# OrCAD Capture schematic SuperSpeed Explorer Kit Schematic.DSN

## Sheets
1 PAGE04: FX3 POWER: size A; title: FX3 DVK; rev: 2.0
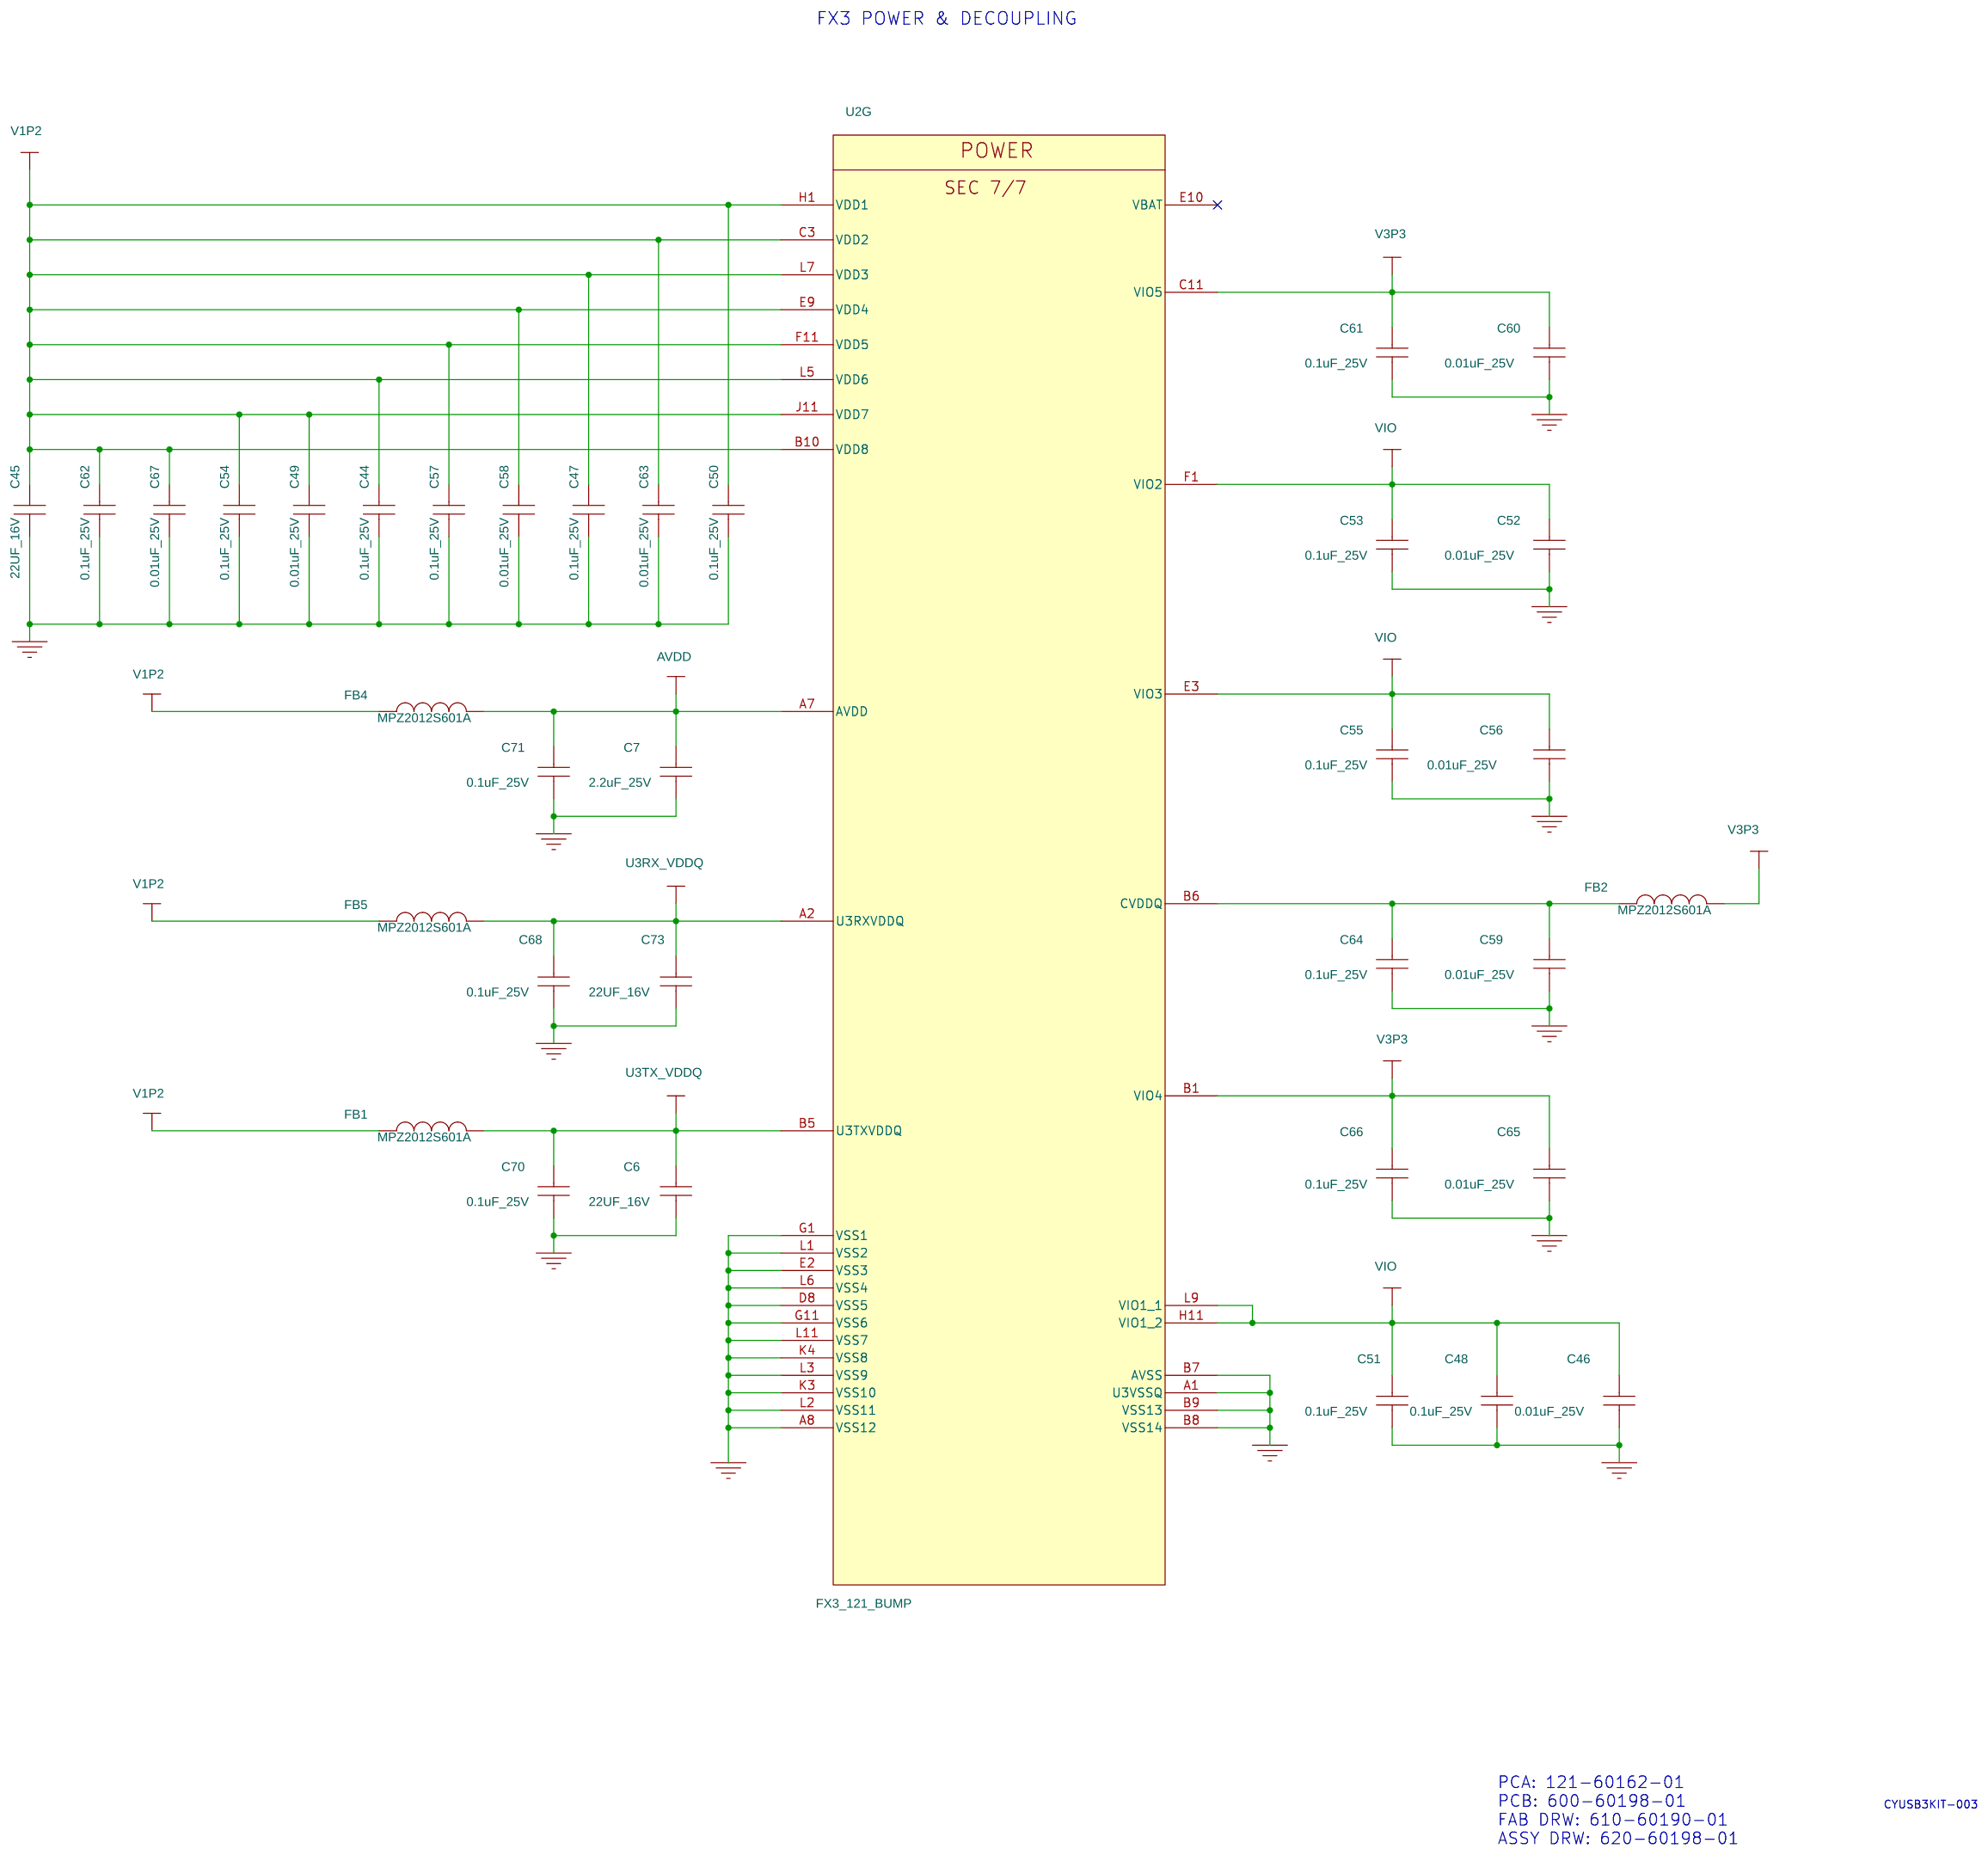
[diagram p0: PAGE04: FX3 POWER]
2 PAGE05: IO PORT1: size A
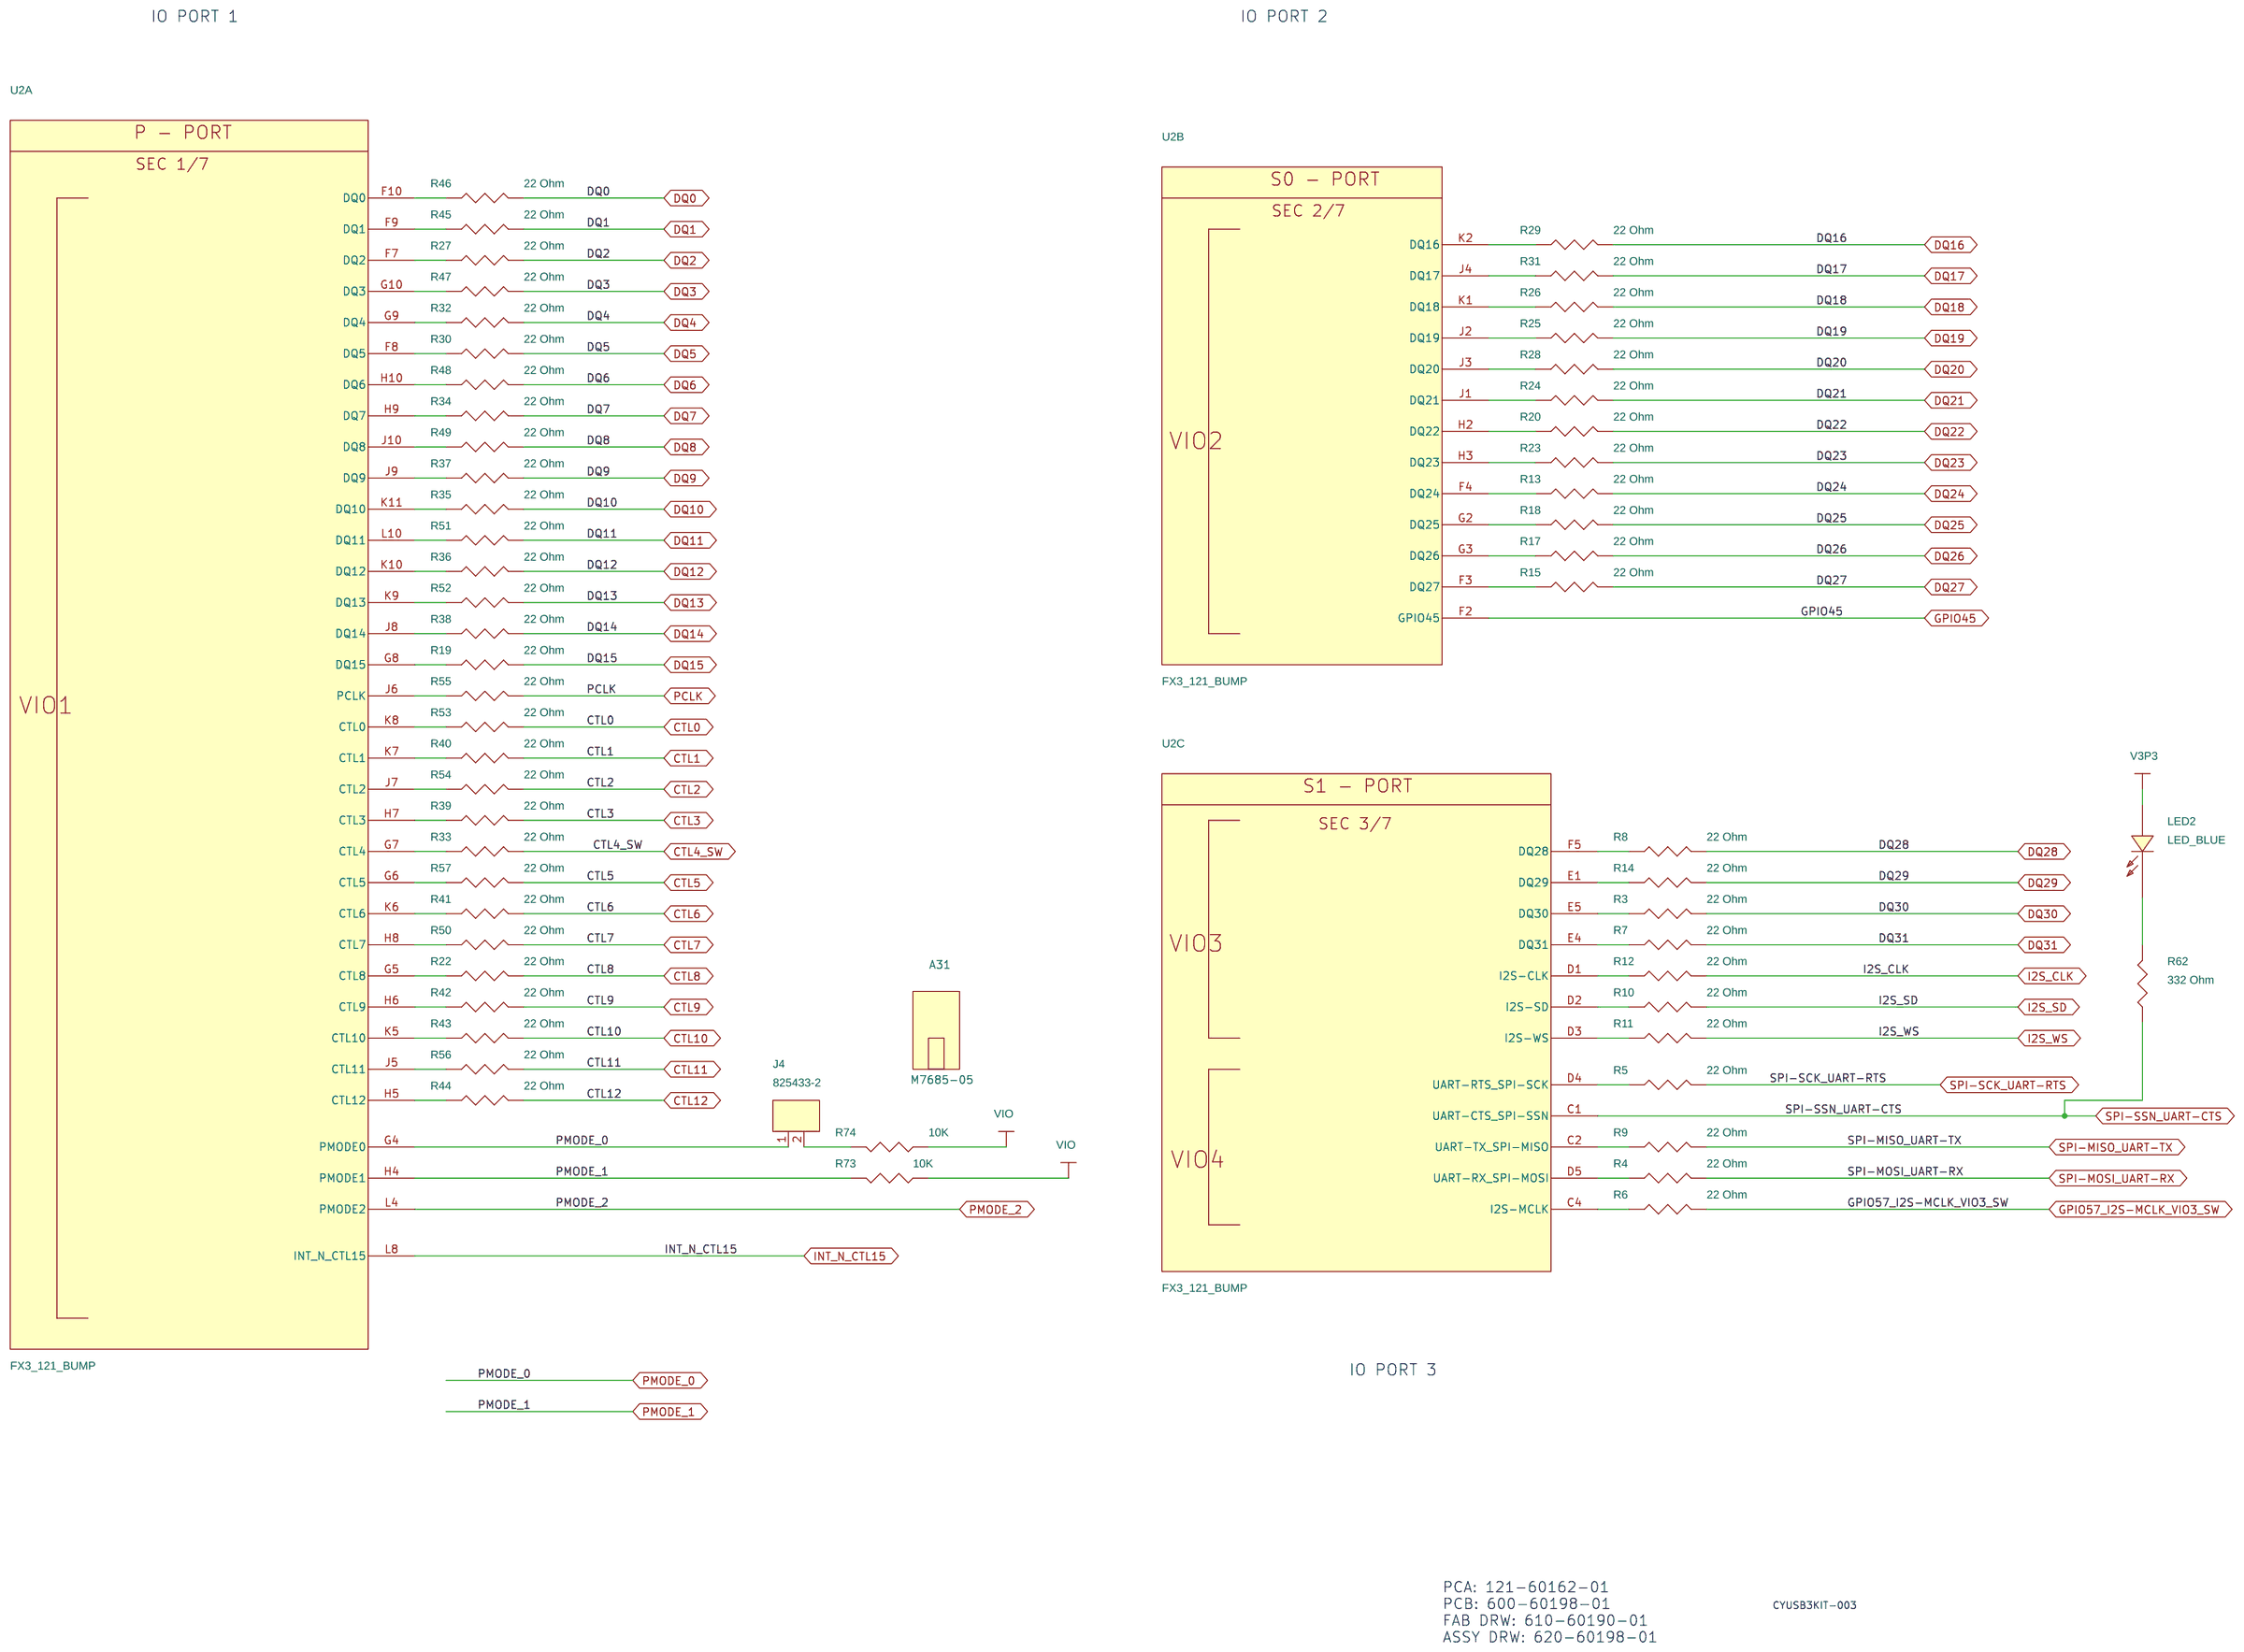
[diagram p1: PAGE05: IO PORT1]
3 PAGE07: SRAM: size A
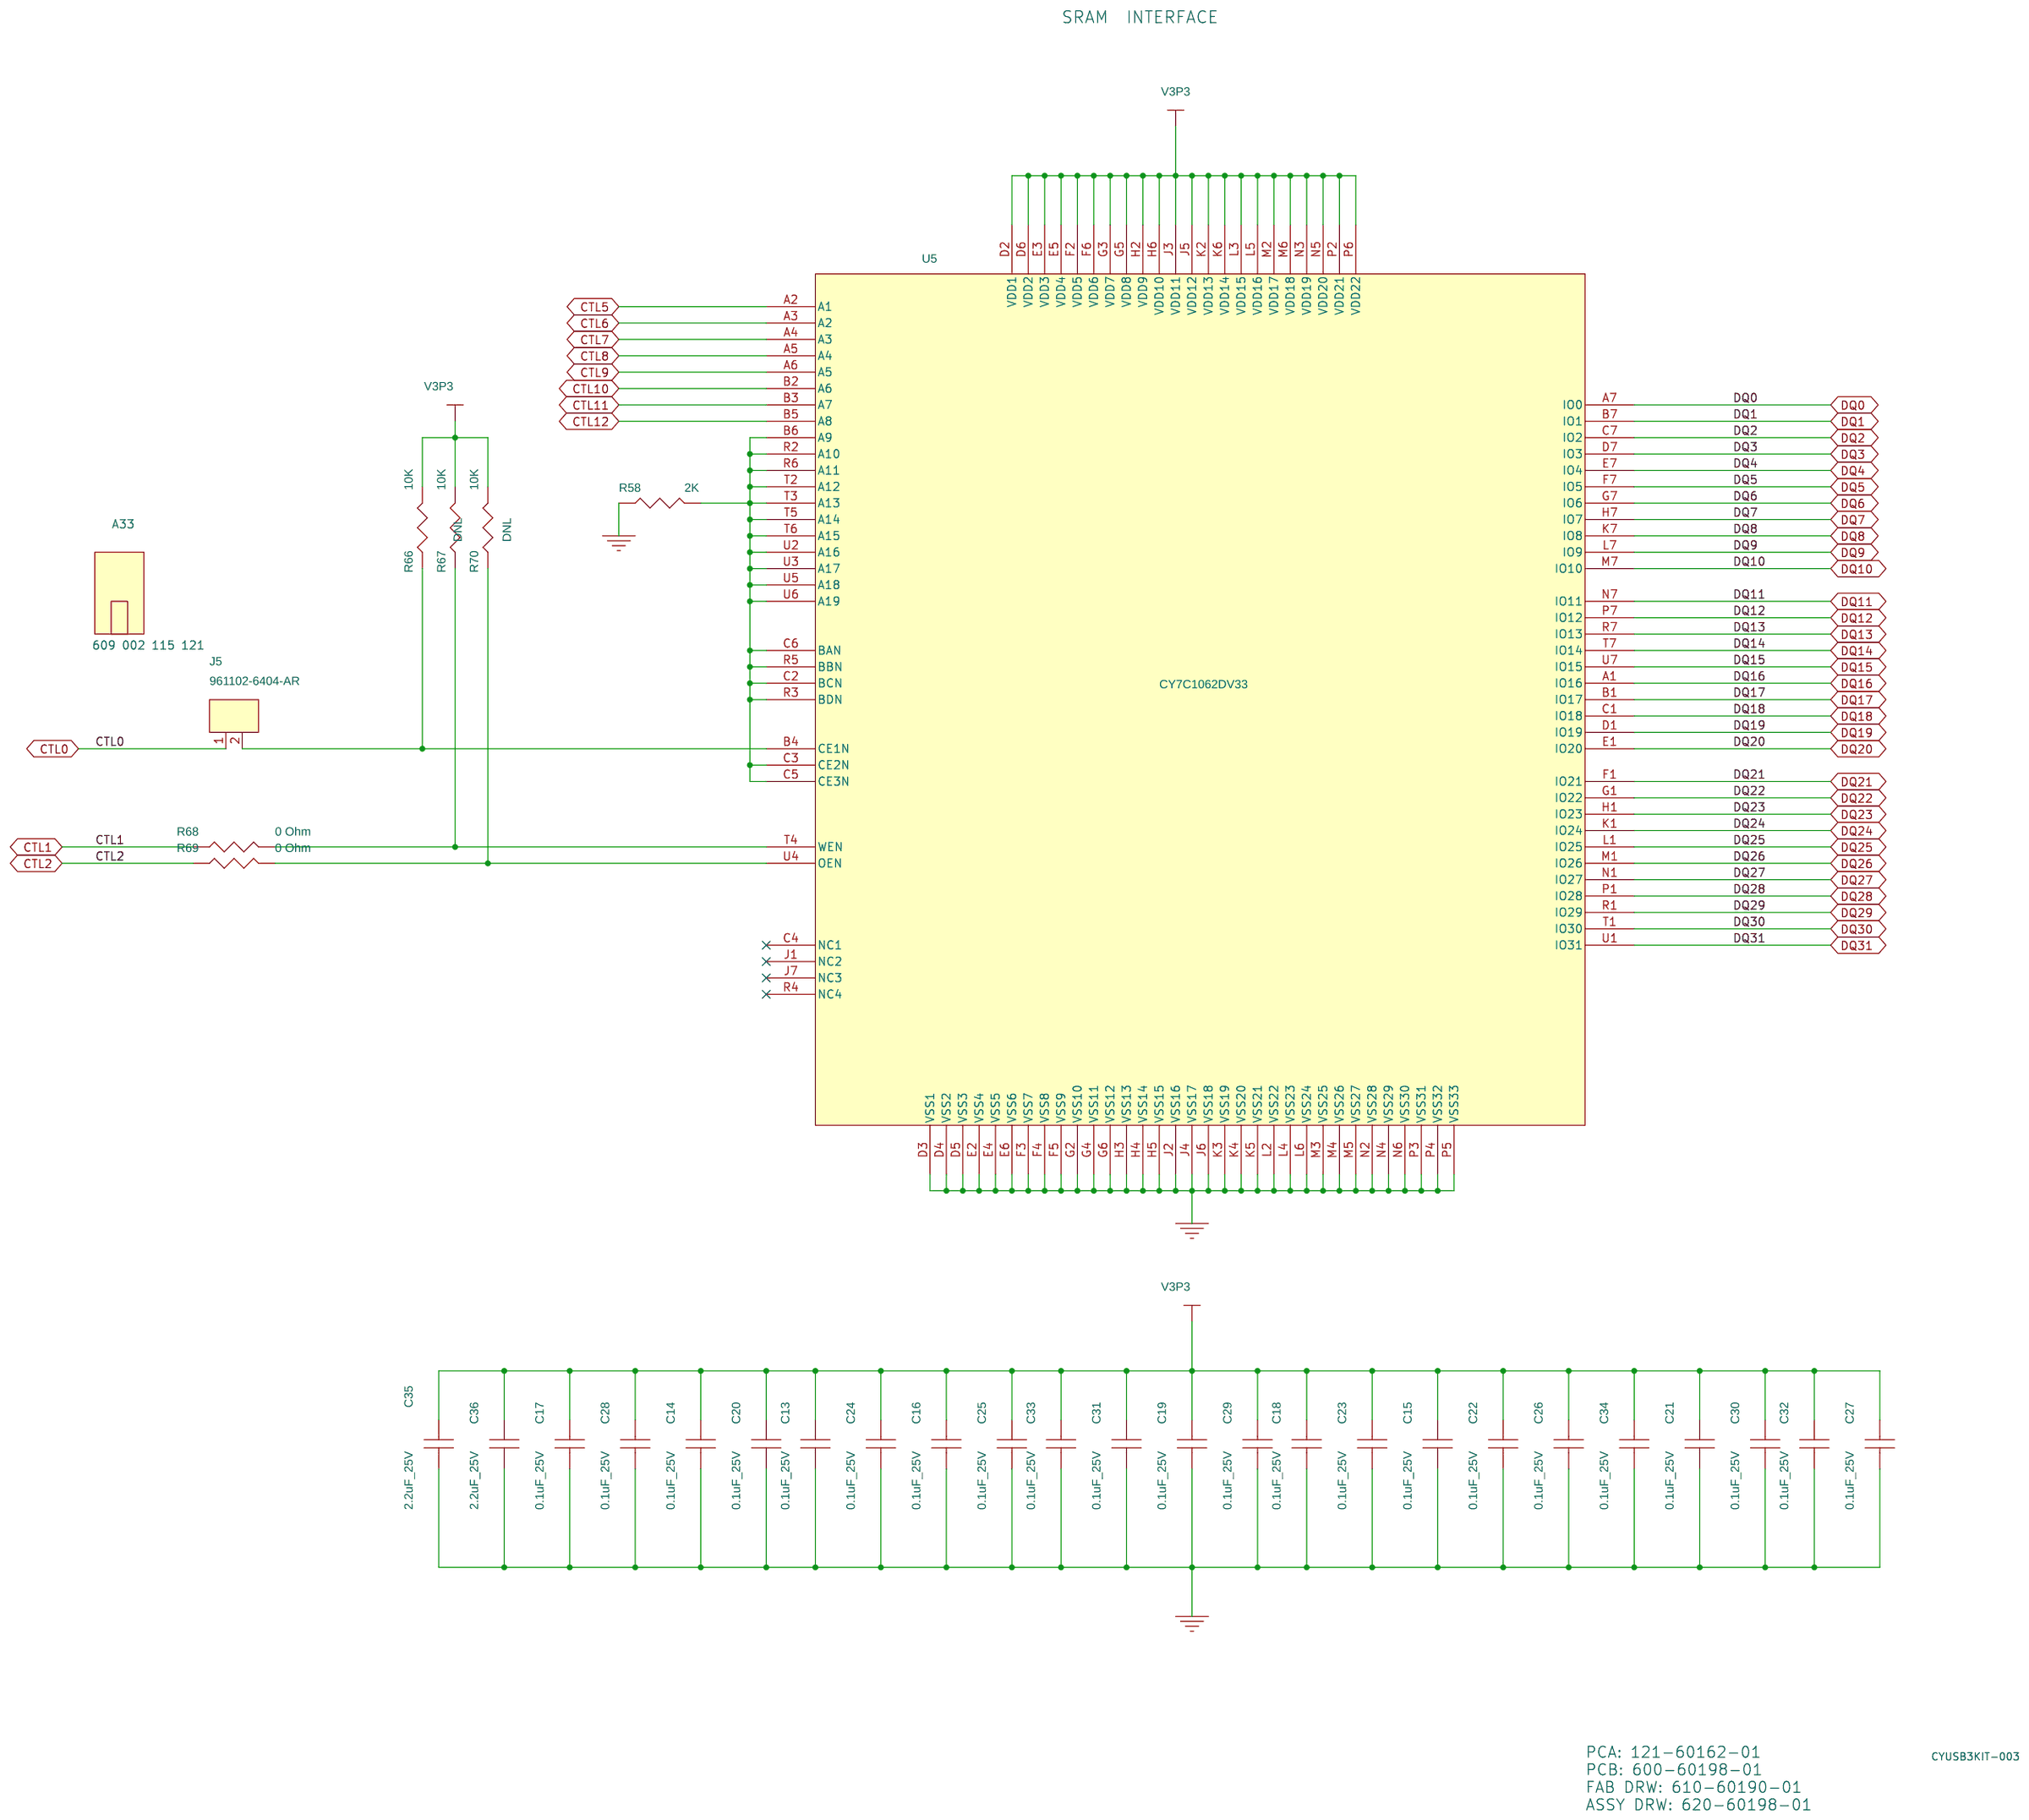
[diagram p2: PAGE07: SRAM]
4 PAGE03: FX3 CLOCK: size A
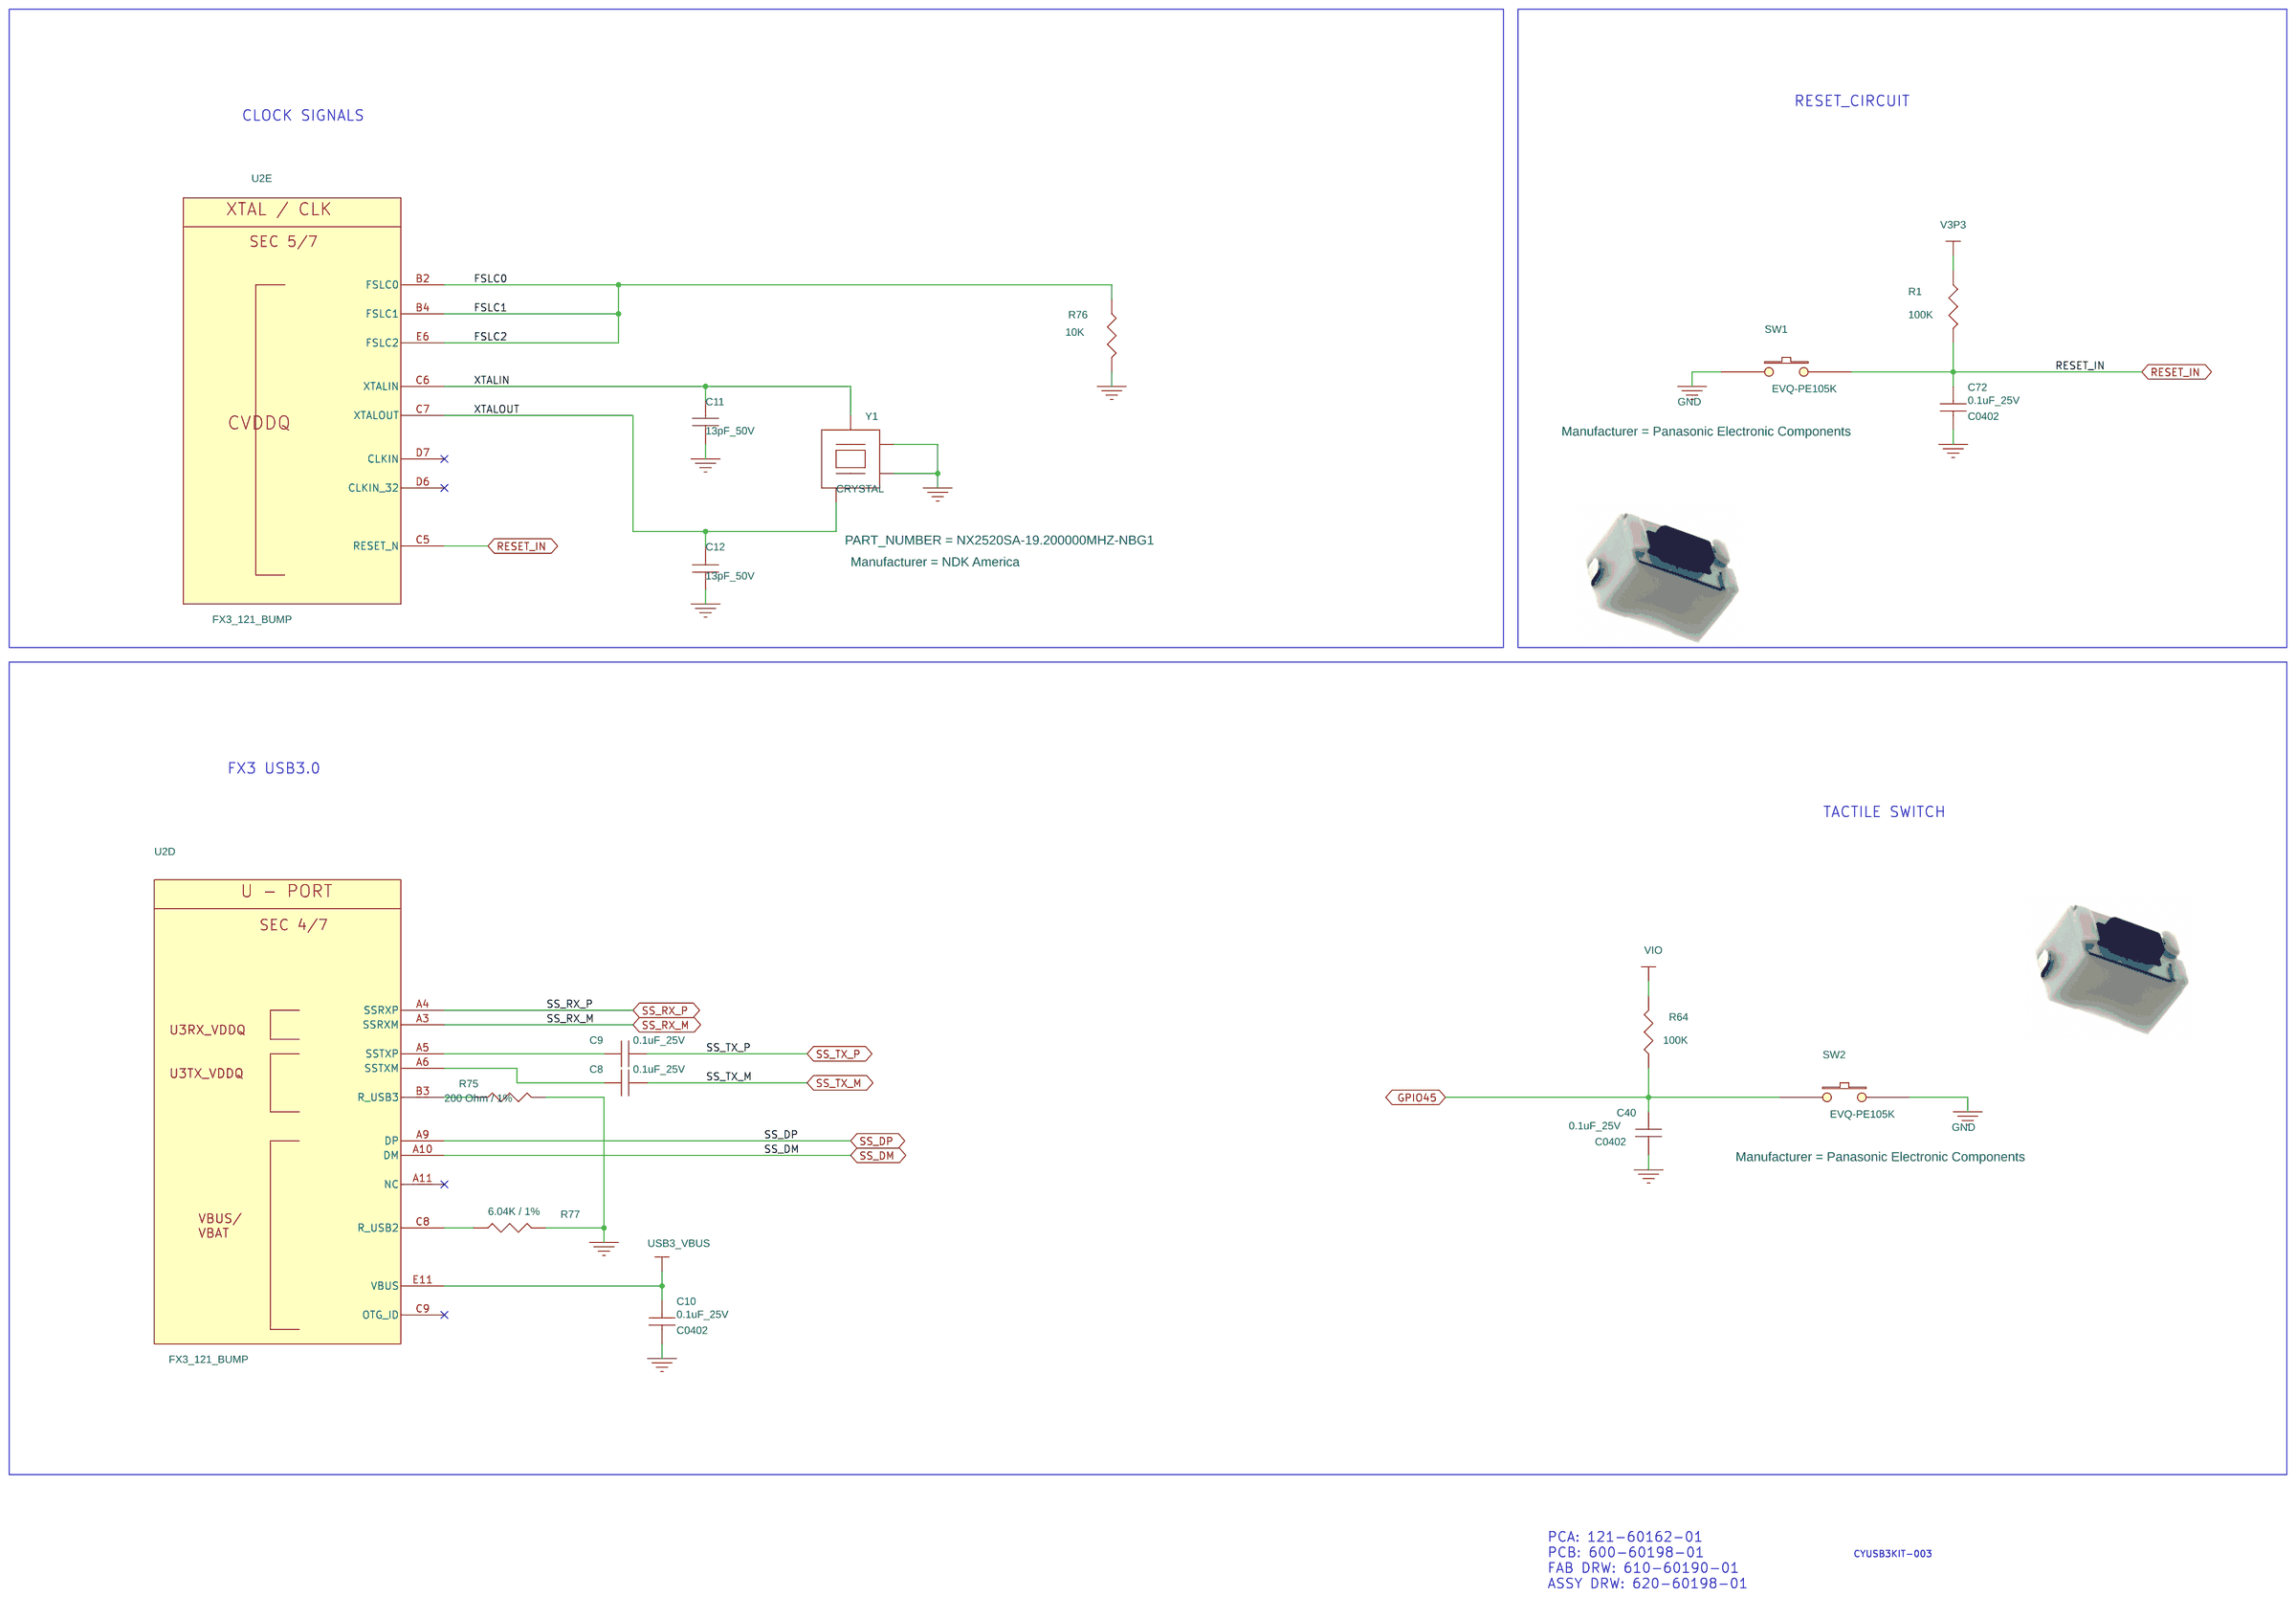
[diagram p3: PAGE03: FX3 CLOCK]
5 PAGE08:UART & JTAG: size A
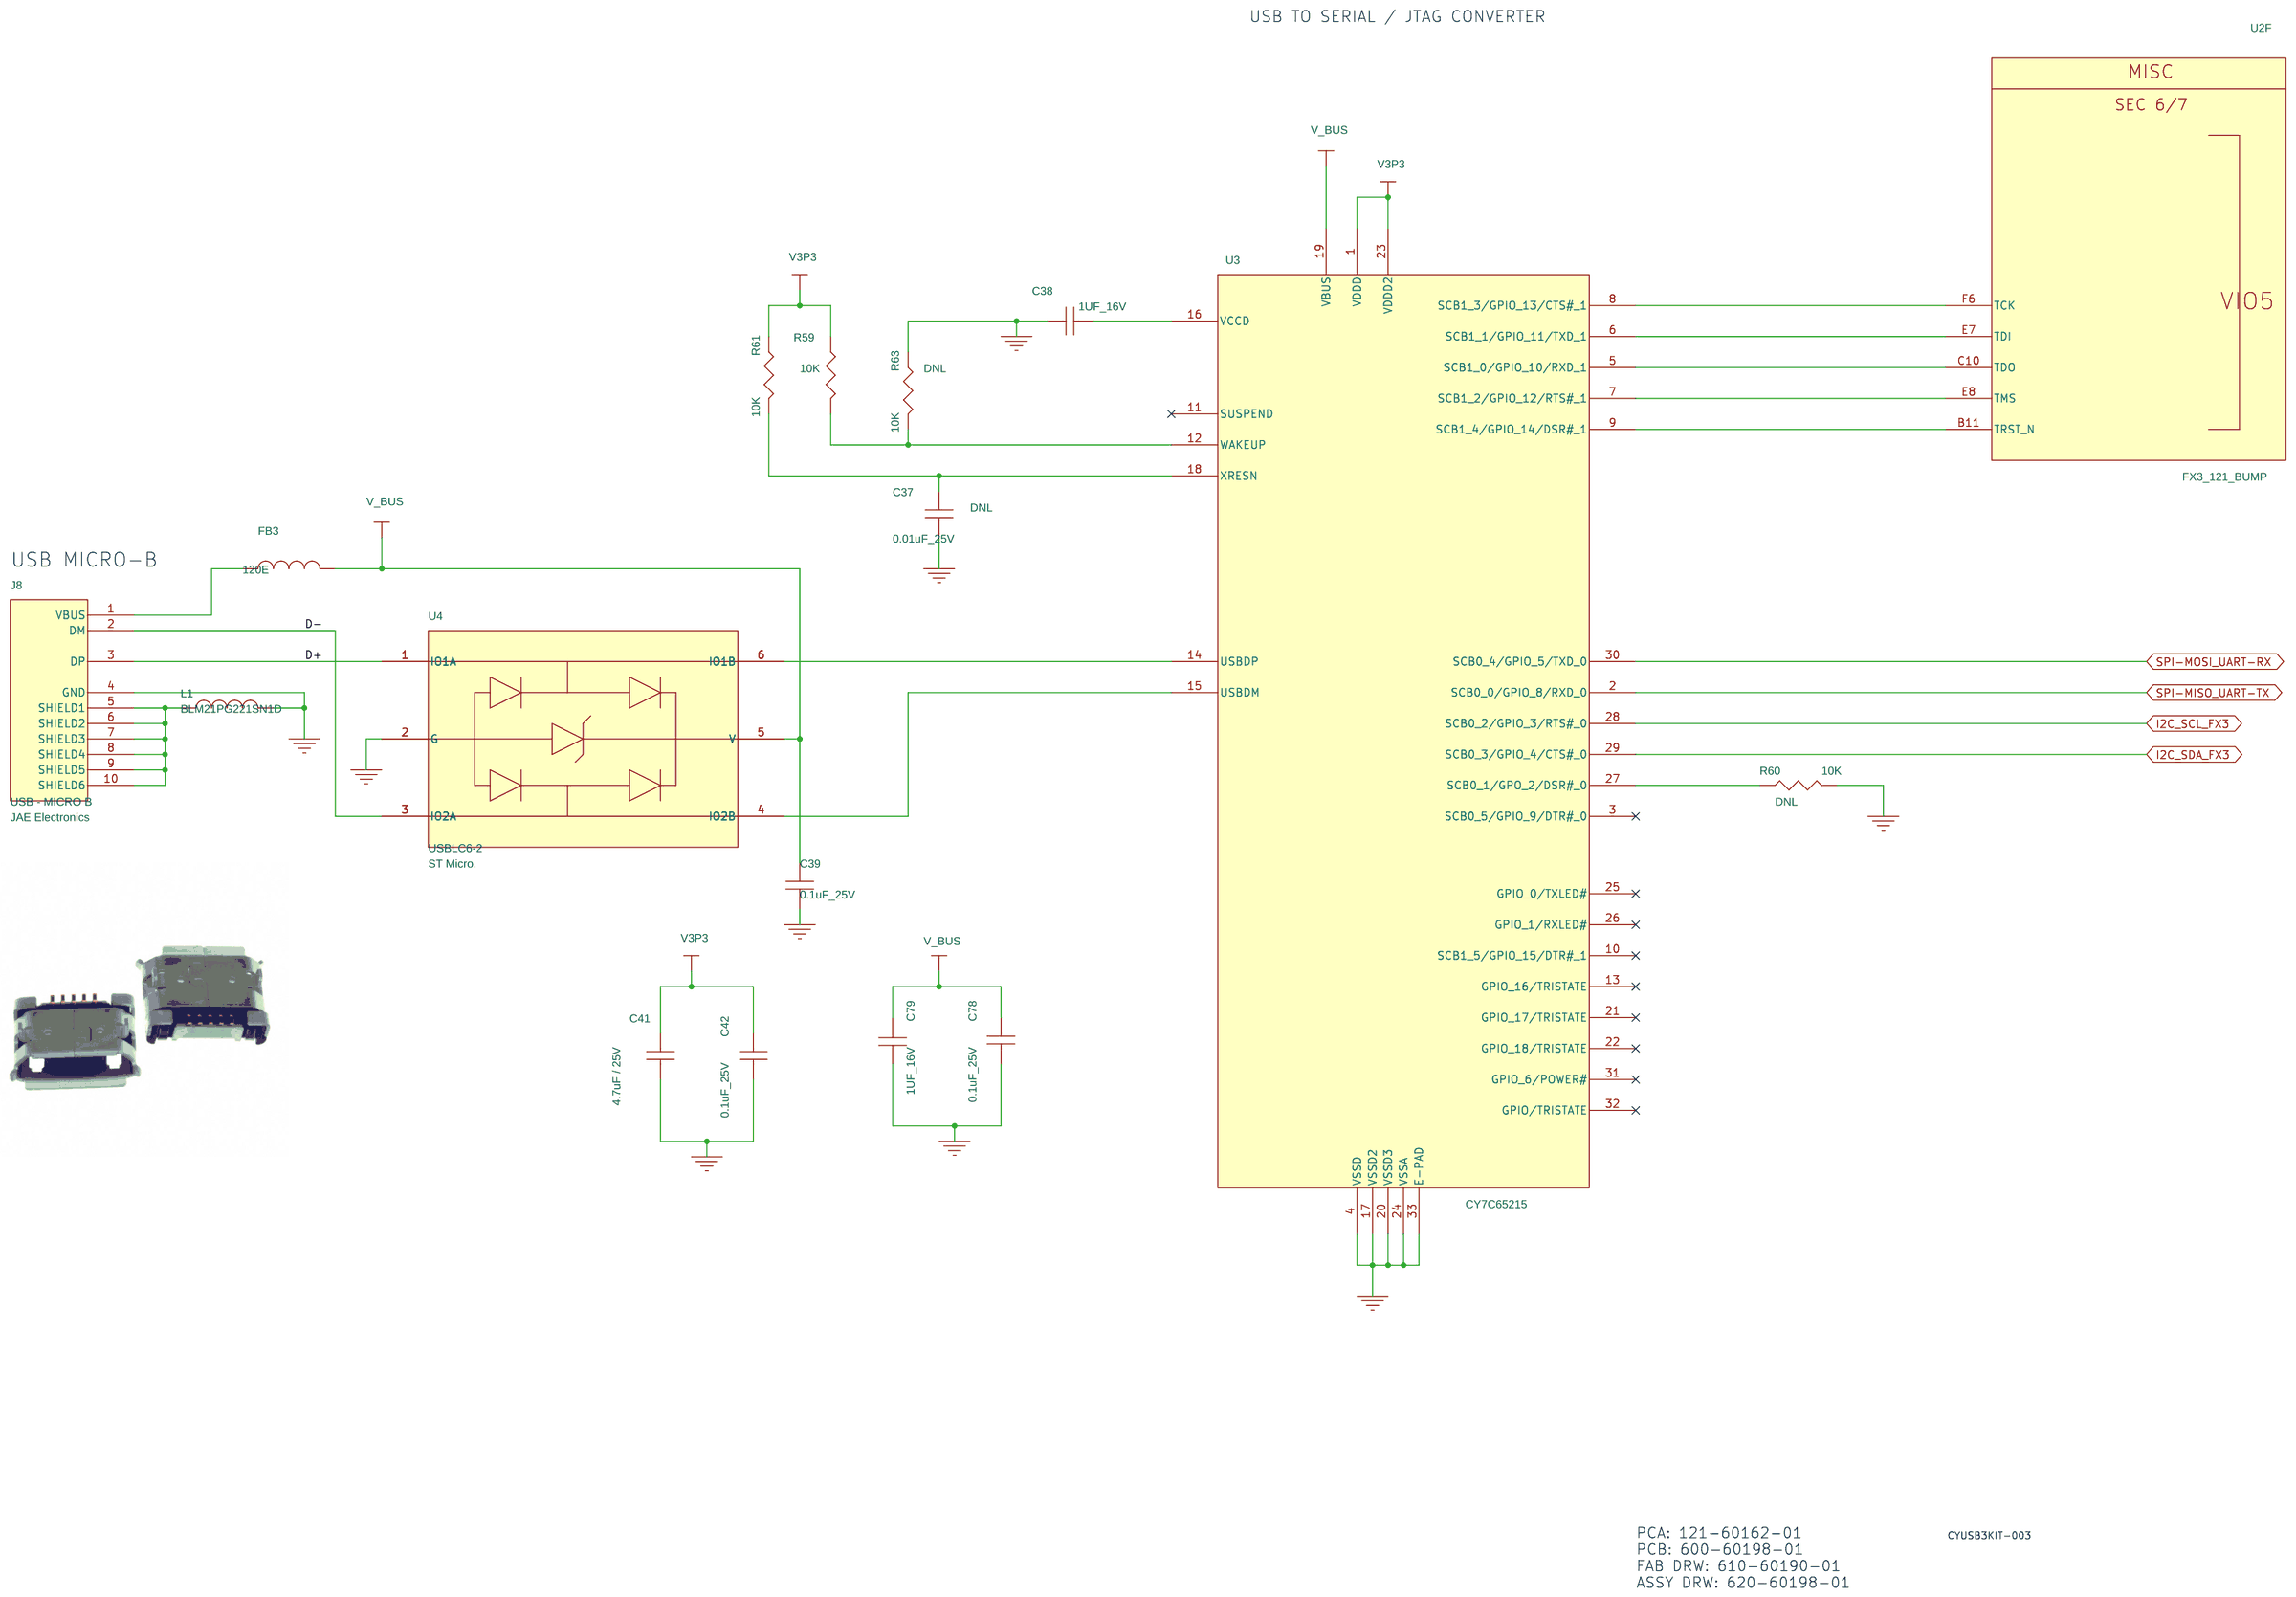
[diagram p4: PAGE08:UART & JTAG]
6 PAGE01: INDEX PAGE
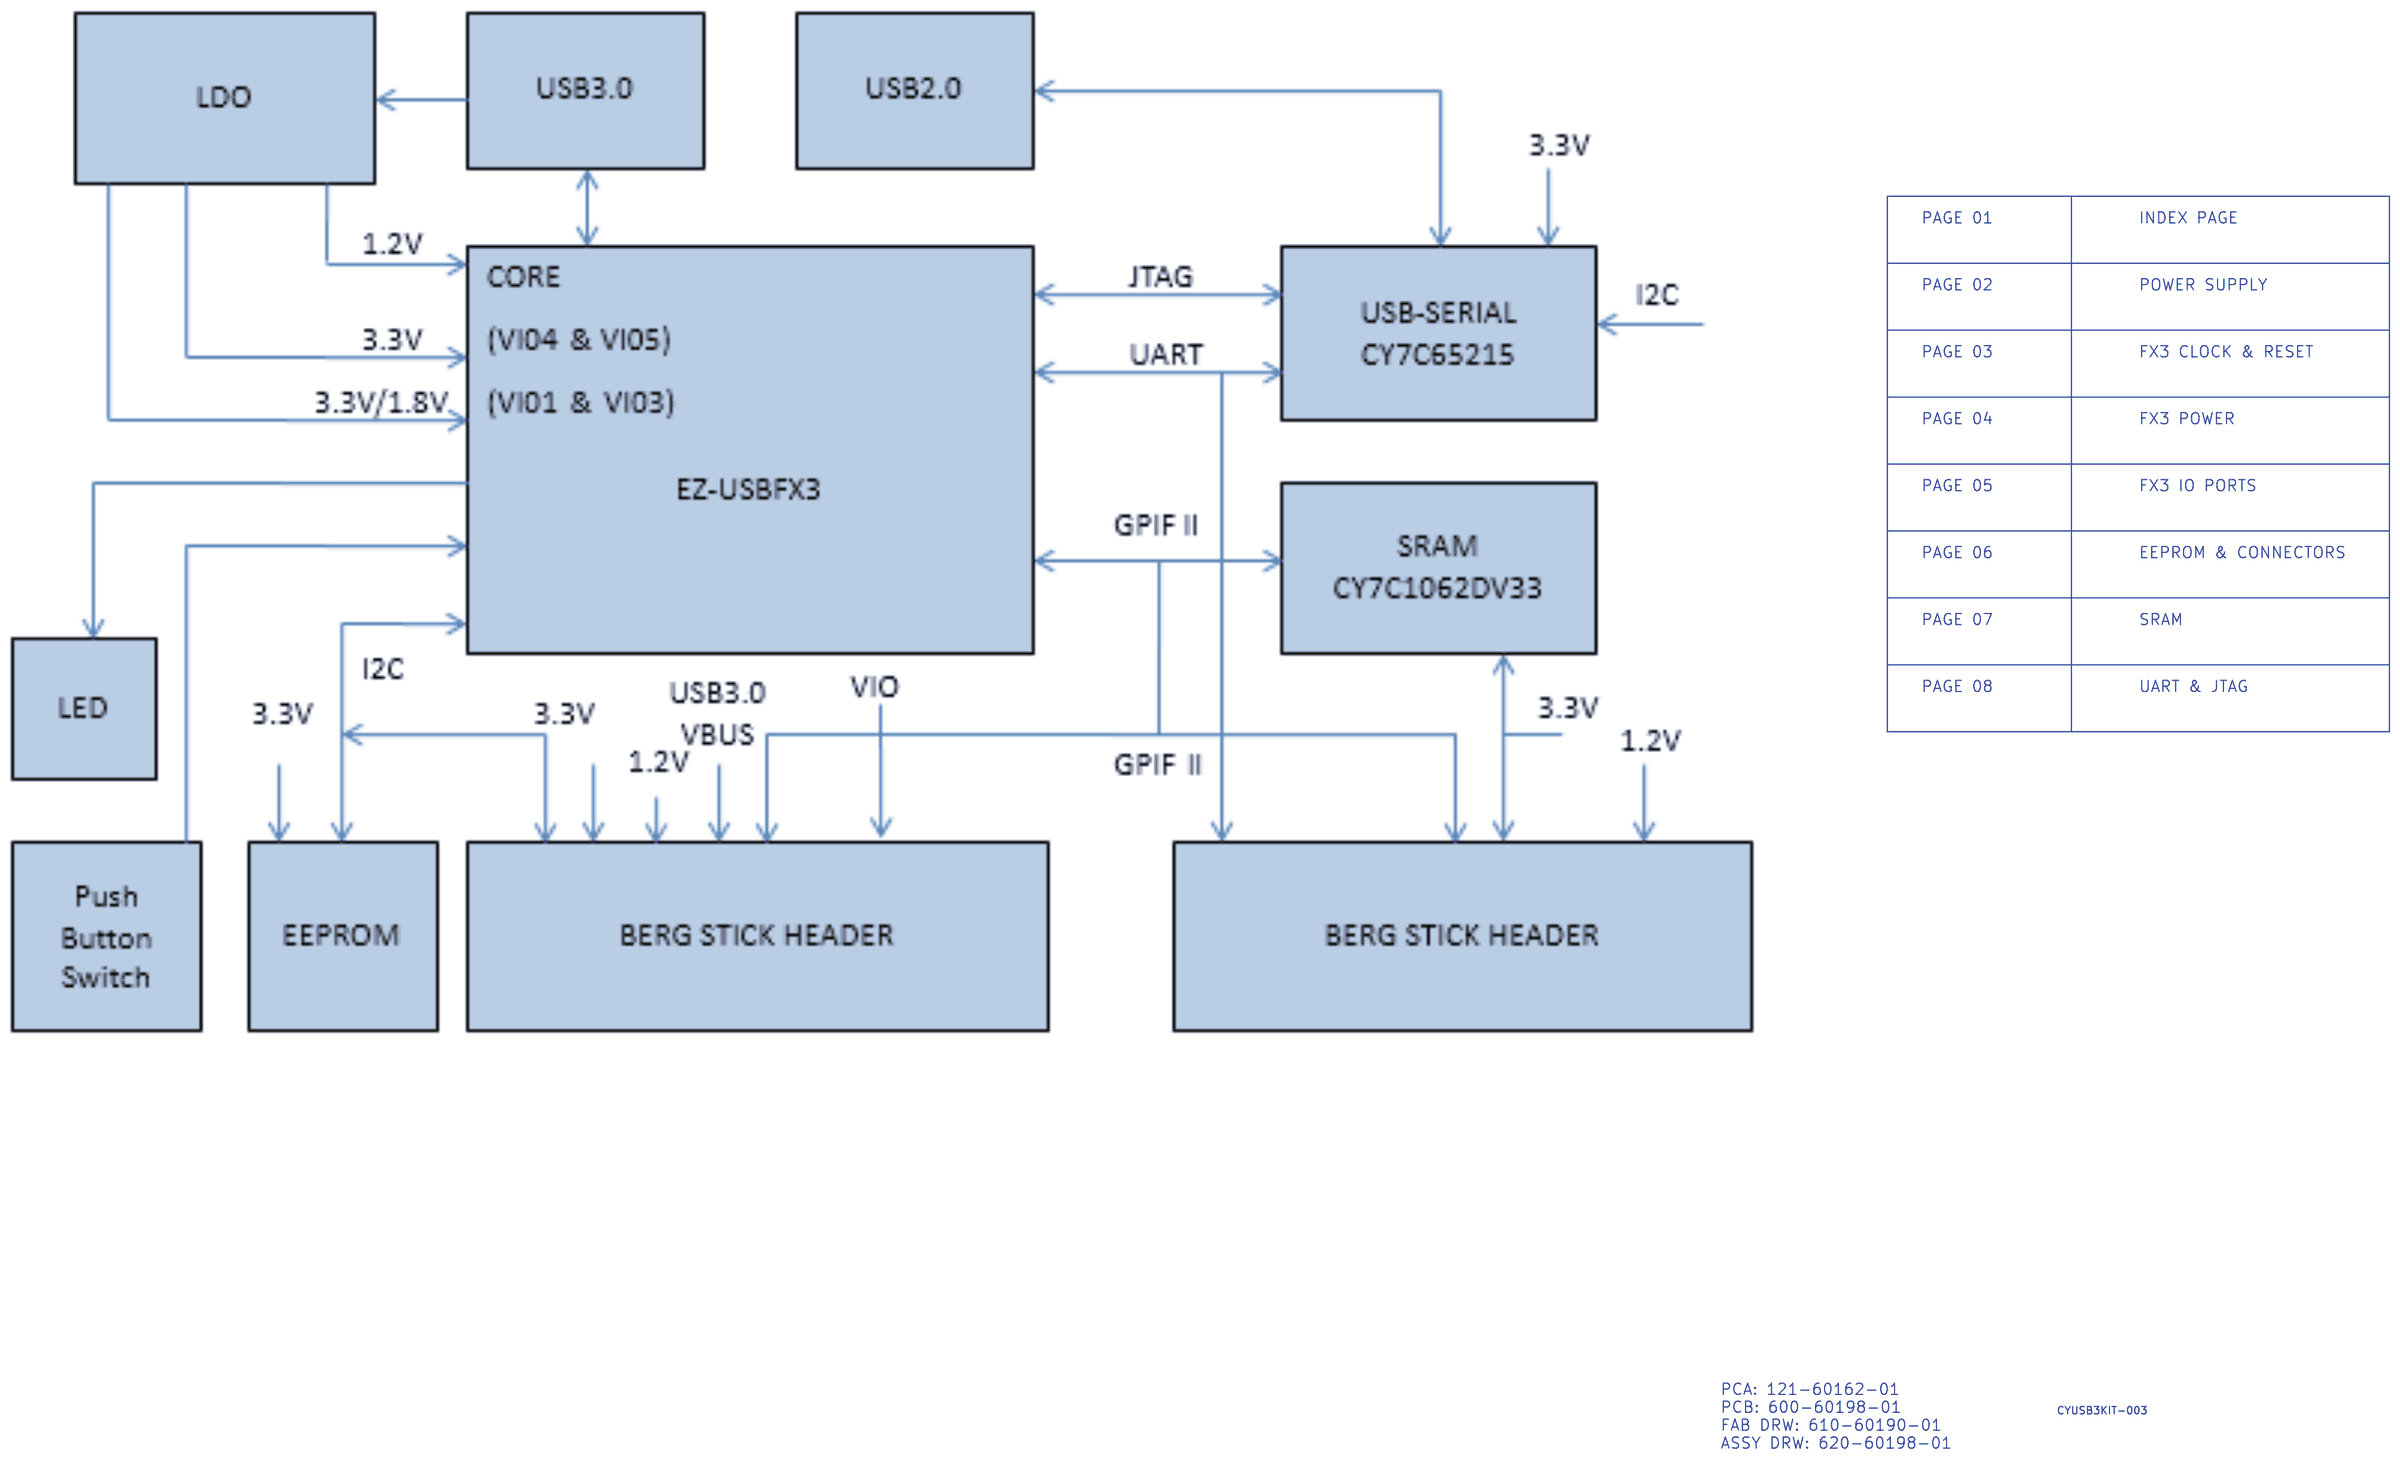
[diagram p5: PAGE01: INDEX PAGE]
7 PAGE02: POWER SUPPLY: size A
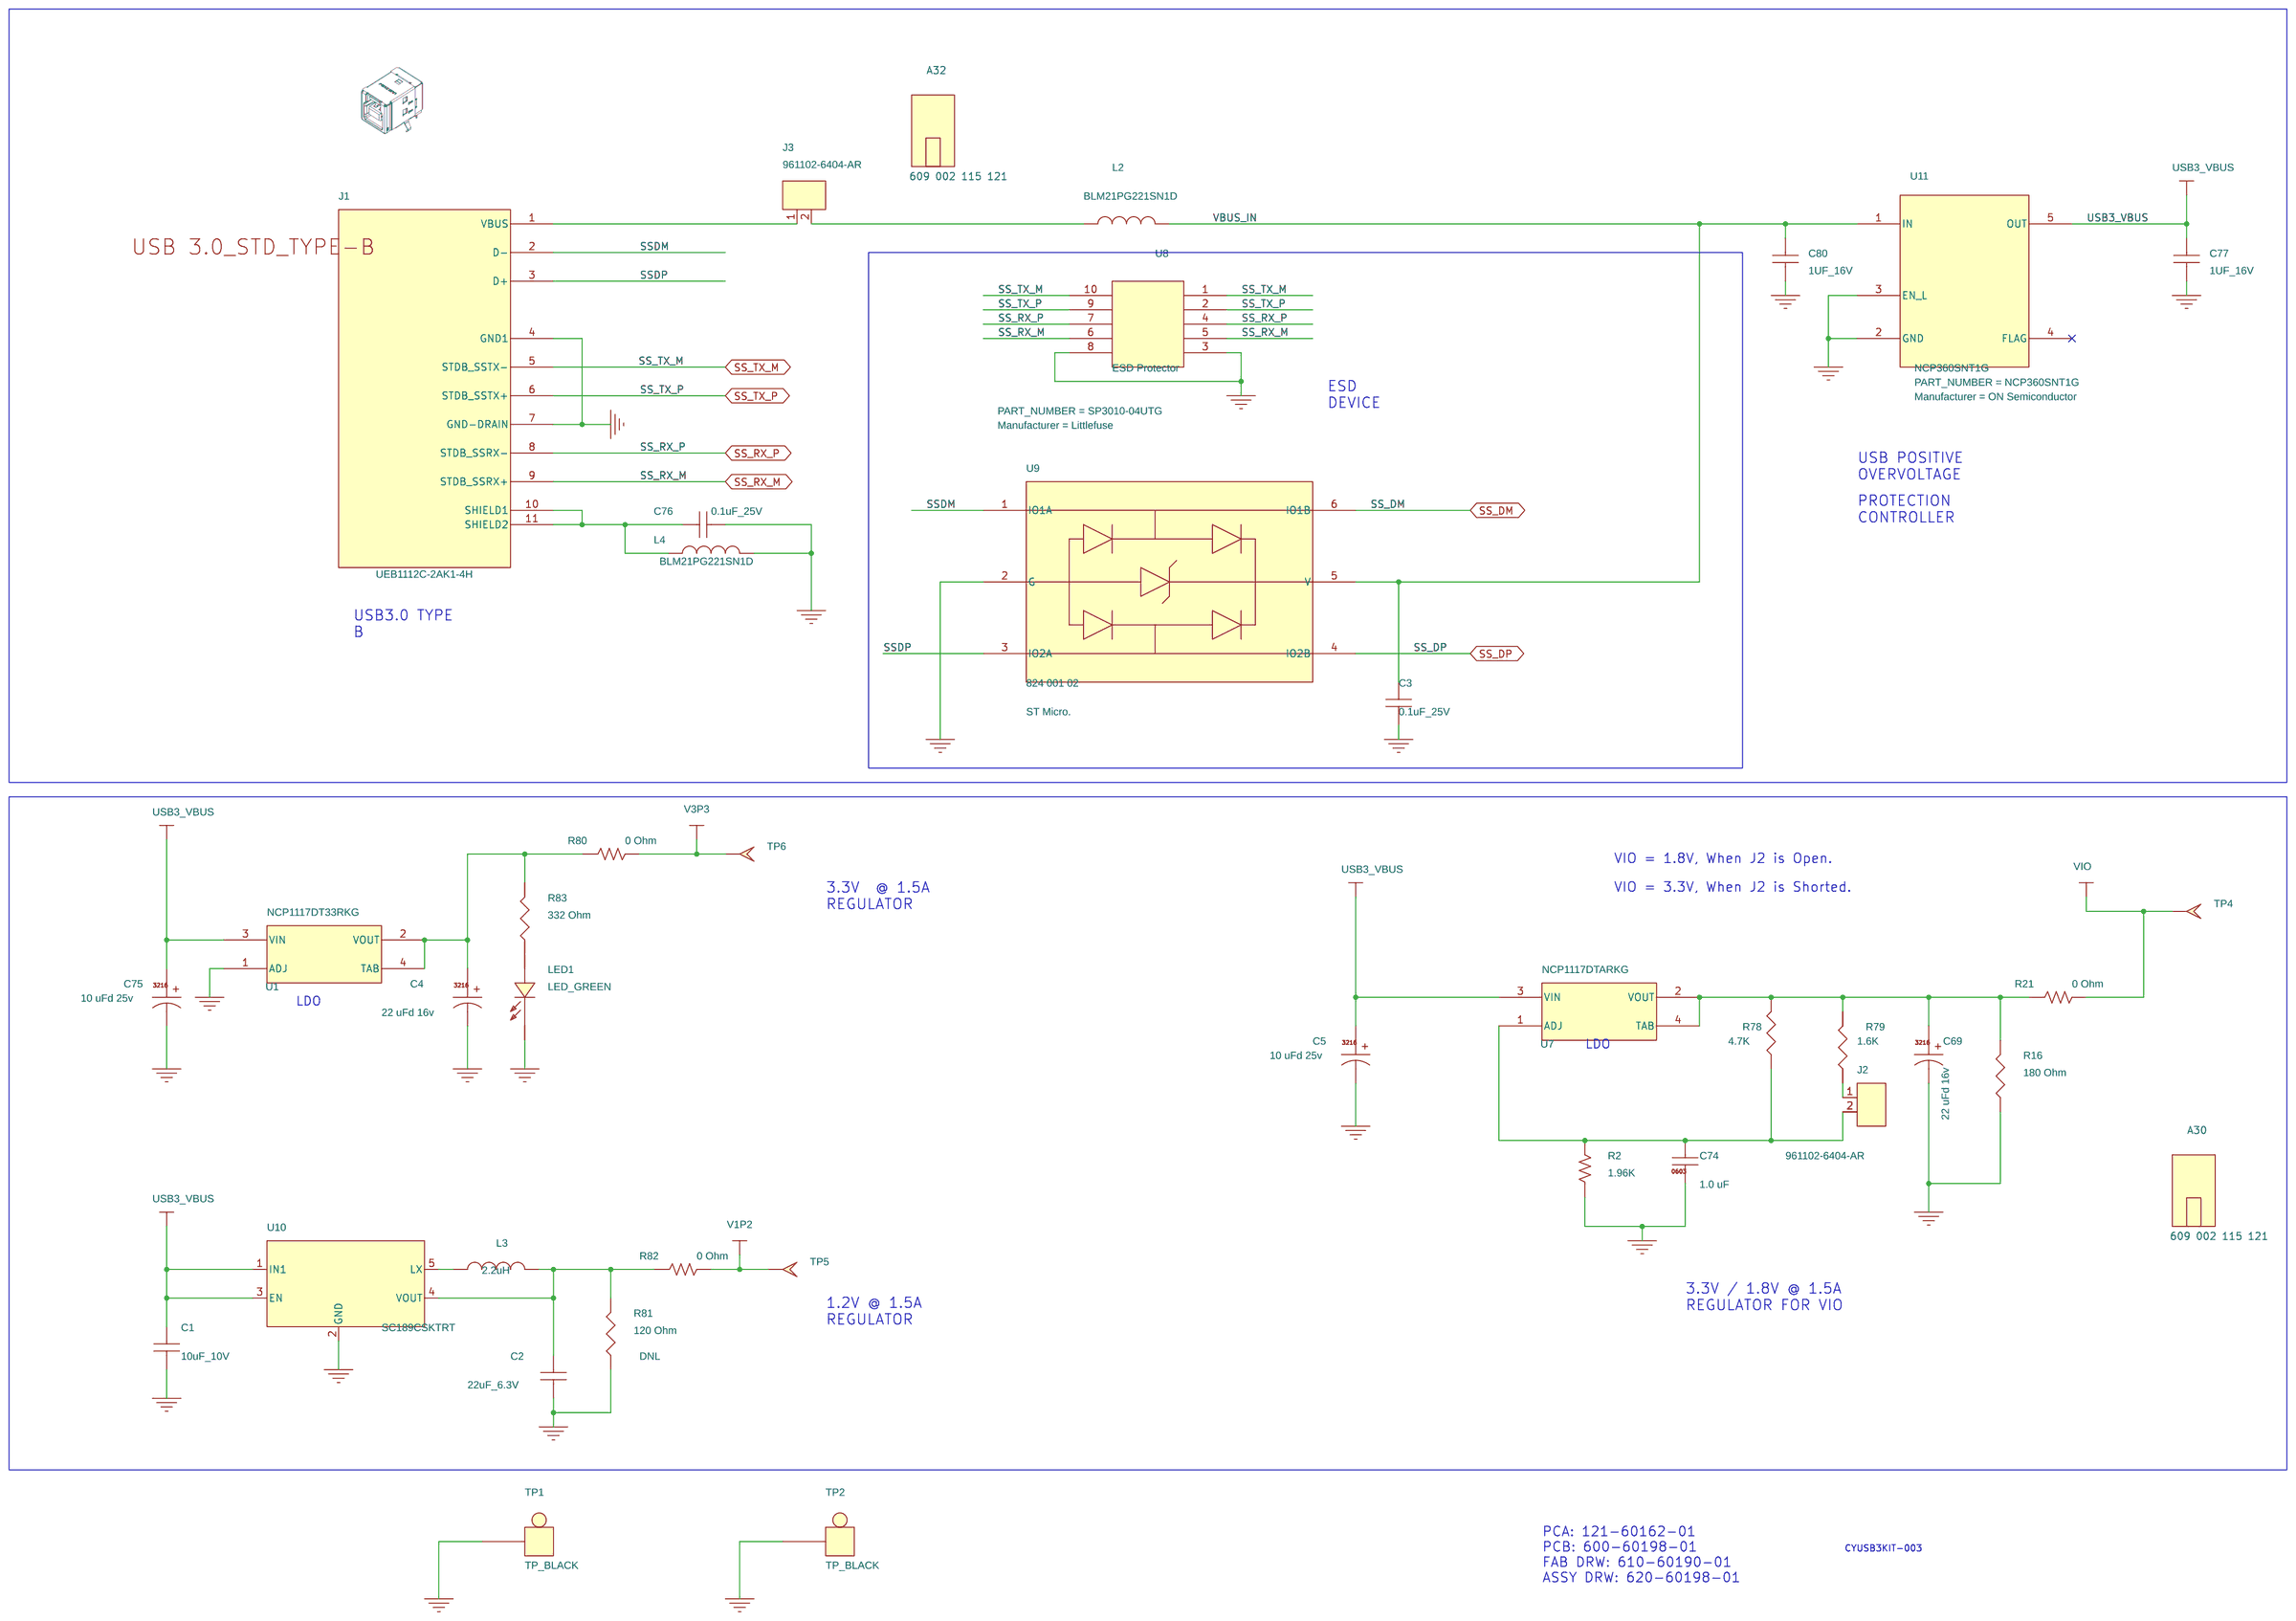
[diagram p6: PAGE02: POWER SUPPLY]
8 PAGE06: I2C EEPROM & CONNECTORS: size A
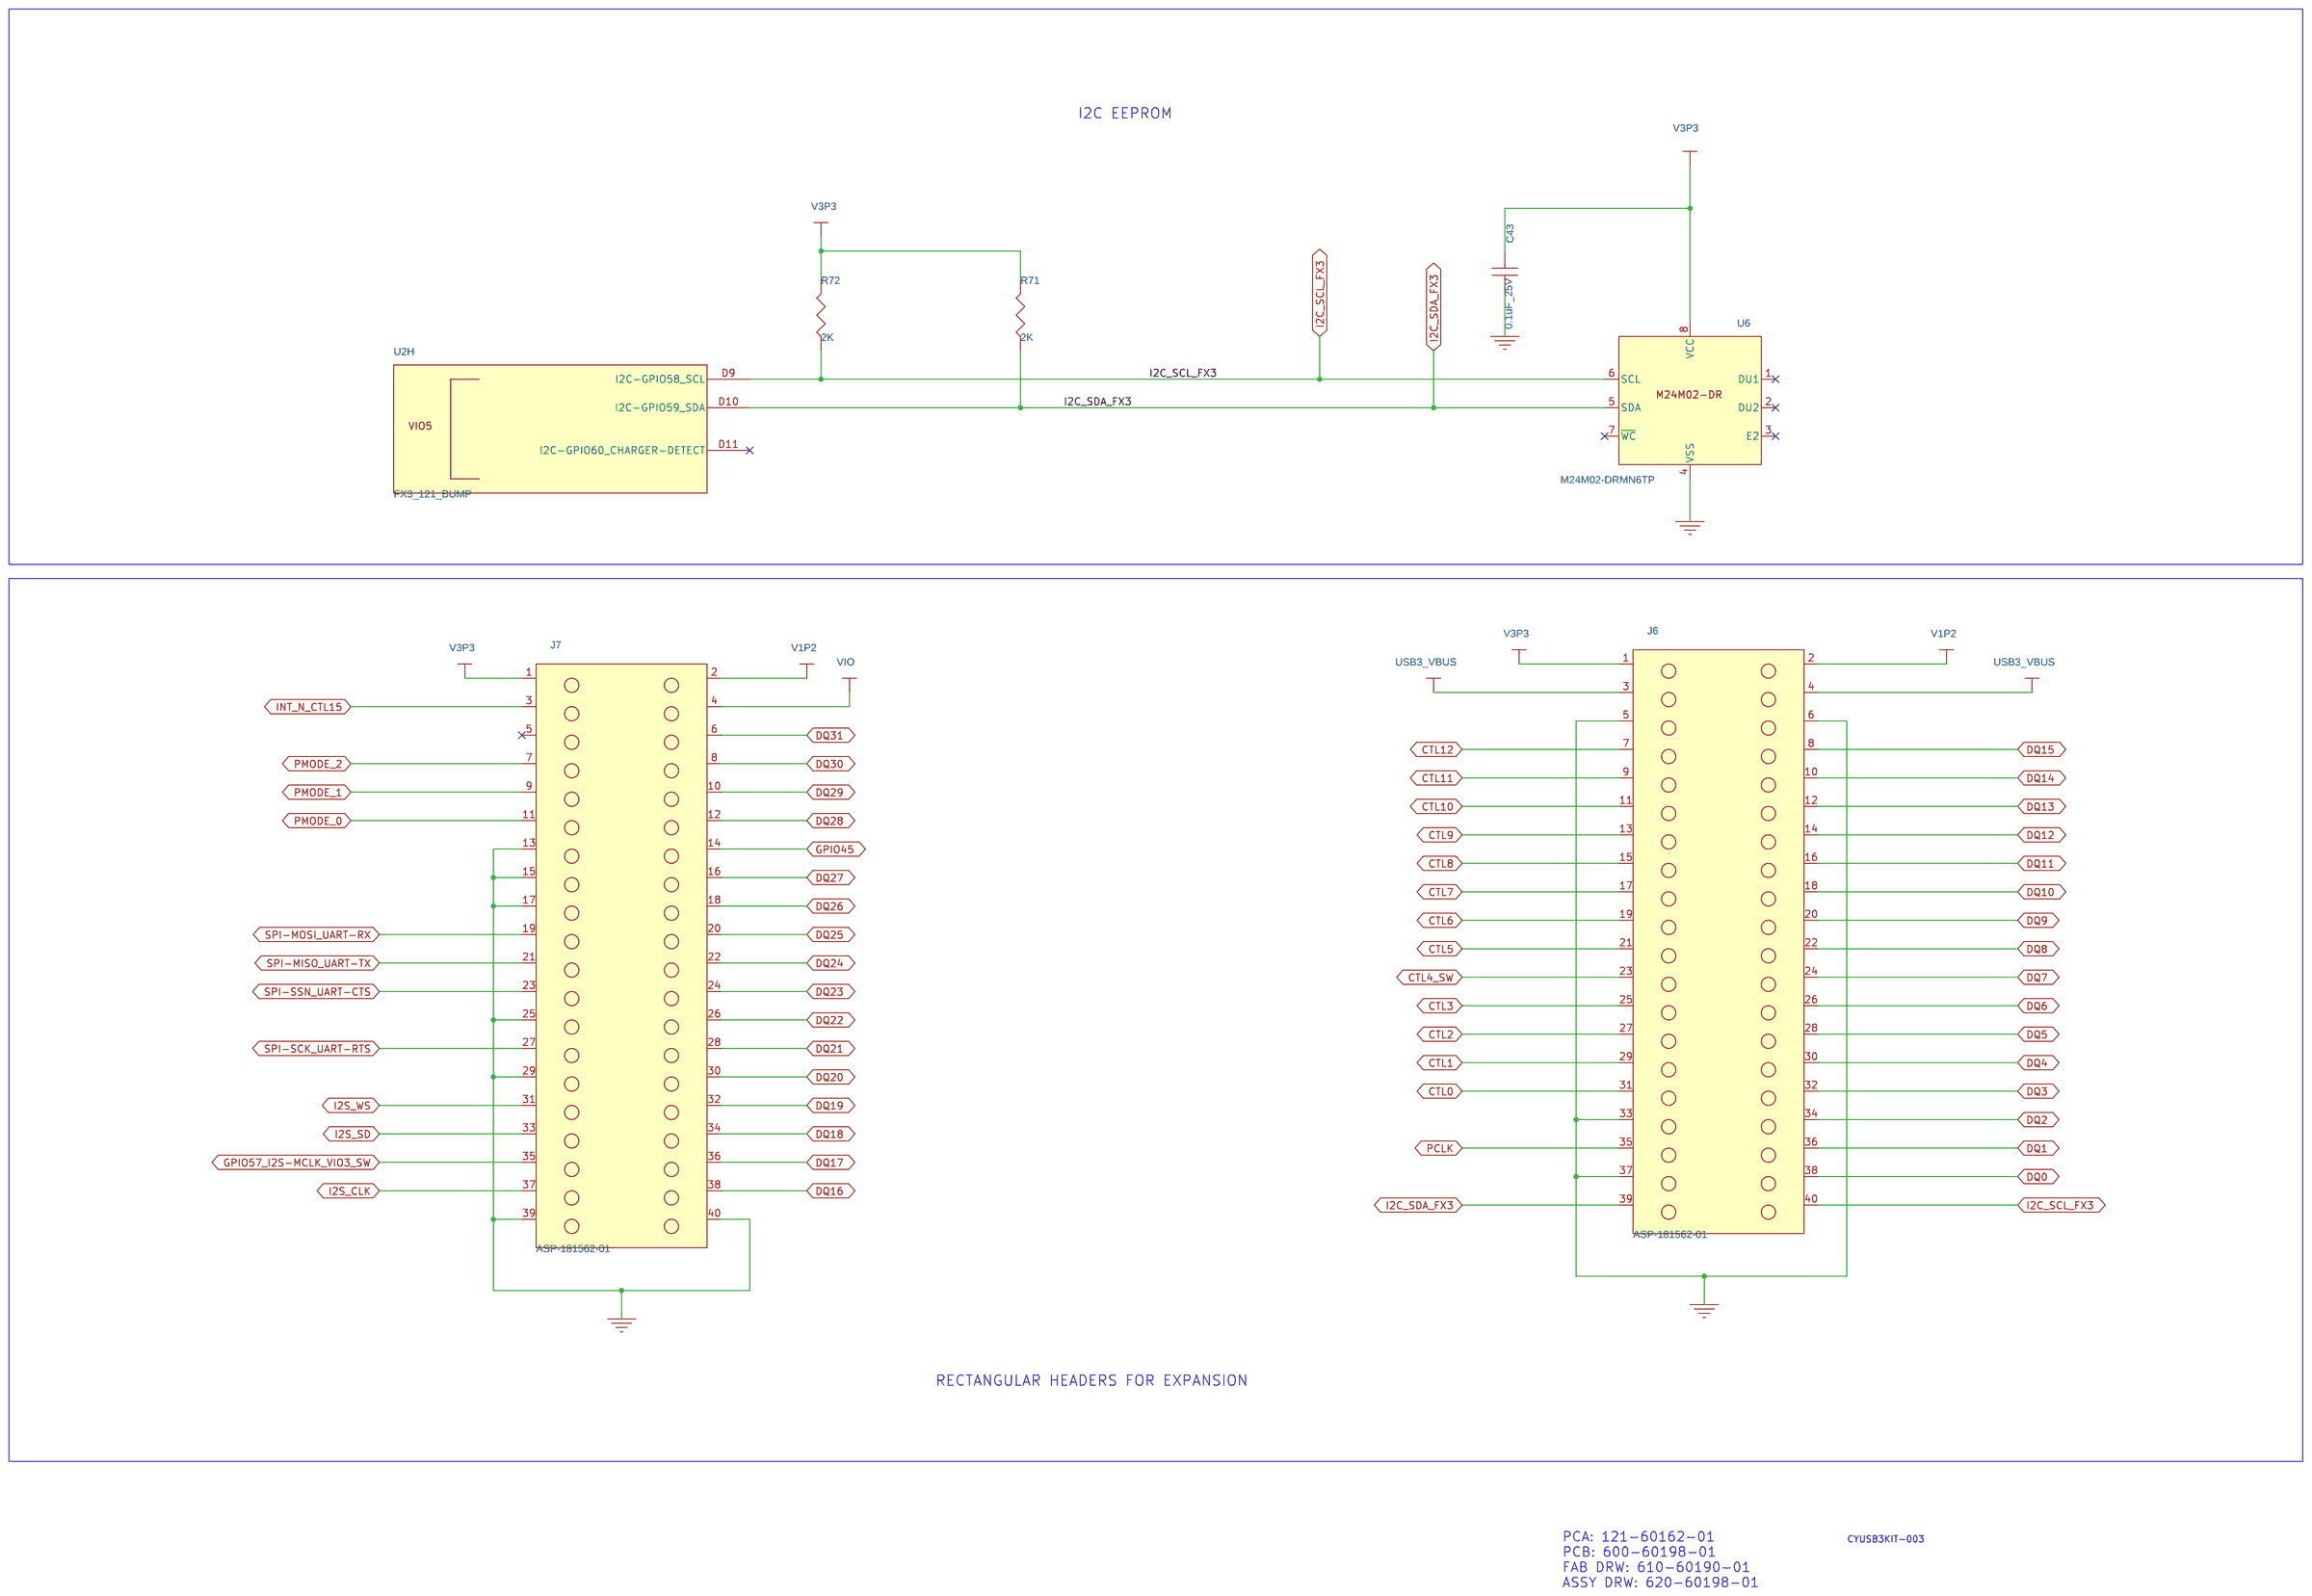
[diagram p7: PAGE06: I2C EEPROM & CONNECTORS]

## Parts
sheet PAGE02: POWER SUPPLY
A30  609 002 115 121  [-]
A32  609 002 115 121  [-]
C1  10uF_10V  [CC0805]
C2  22uF_6.3V  [CC1206]
C3  0.1uF_25V  [C0402]
C4  22 uFd 16v  [c-pcc3528]
C5  10 uFd 25v  [c-pcc3528]
C69  22 uFd 16v  [c-pcc3528]
C74  1.0 uF  [CAPC1608X90N]
C75  10 uFd 25v  [c-pcc3528]
C76  0.1uF_25V  [C0402]
C77  1UF_16V  [CC0603]
C80  1UF_16V  [CC0603]
J1  UEB1112C-2AK1-4H  [UEB1112C-2AK1-4H]
J2  961102-6404-AR  [TE_825433-2]
J3  961102-6404-AR  [TE_825433-2]
L2  BLM21PG221SN1D  [BLM21PG221SN1D]
L3  2.2uH  [NLCV32T-2R2M-PFR]
L4  BLM21PG221SN1D  [BLM21PG221SN1D]
LED1  LED_GREEN  [LED_0603]
R2  1.96K  [R0402]
R16  180 Ohm  [R0402]
R21  0 Ohm  [RES0805]
R78  4.7K  [R0402]
R79  1.6K  [R0402]
R80  0 Ohm  [RES0805]
R81  120 Ohm  [R0402]
R82  0 Ohm  [RES0805]
R83  332 Ohm  [R0402]
TP1  TP_BLACK  [TP_RED_5001]
TP2  TP_BLACK  [TP_RED_5001]
TP4  TP_4060  [TP100_200MASK]
TP5  TP_4060  [TP100_200MASK]
TP6  TP_4060  [TP100_200MASK]
U1  NCP1117DT33RKG  [DPAK_4PIN_REL]
U7  NCP1117DTARKG  [DPAK_4PIN_REL]
U8  ESD Protector  [UDFN10_SP3010]
U9  824 001 02  [SOT95P280X145-6N]
U10  SC189CSKTRT  [SOT95P280X145-5N]
U11  NCP360SNT1G  [SOT95P275X110-5N]
sheet PAGE03: FX3 CLOCK
C8  0.1uF_25V  [C0402]
C9  0.1uF_25V  [C0402]
C10  0.1uF_25V  [C0402]
C11  13pF_50V  [C0402]
C12  13pF_50V  [C0402]
C40  0.1uF_25V  [C0402]
C72  0.1uF_25V  [C0402]
R1  100K  [R0402]
R64  100K  [R0402]
R75  200 Ohm / 1%  [R0402]
R76  10K  [R0402]
R77  6.04K / 1%  [R0402]
SW1  EVQ-PE105K  [EVQ-PE105K]
SW2  EVQ-PE105K  [EVQ-PE105K]
Y1  CRYSTAL  [OSCCC200X250X55-4N]
sheet PAGE04: FX3 POWER
C6  22UF_16V  [C0805]
C7  2.2uF_25V  [C0603]
C44  0.1uF_25V  [C0402]
C45  22UF_16V  [C0805]
C46  0.01uF_25V  [C0402]
C47  0.1uF_25V  [C0402]
C48  0.1uF_25V  [C0402]
C49  0.01uF_25V  [C0402]
C50  0.1uF_25V  [C0402]
C51  0.1uF_25V  [C0402]
C52  0.01uF_25V  [C0402]
C53  0.1uF_25V  [C0402]
C54  0.1uF_25V  [C0402]
C55  0.1uF_25V  [C0402]
C56  0.01uF_25V  [C0402]
C57  0.1uF_25V  [C0402]
C58  0.01uF_25V  [C0402]
C59  0.01uF_25V  [C0402]
C60  0.01uF_25V  [C0402]
C61  0.1uF_25V  [C0402]
C62  0.1uF_25V  [C0402]
C63  0.01uF_25V  [C0402]
C64  0.1uF_25V  [C0402]
C65  0.01uF_25V  [C0402]
C66  0.1uF_25V  [C0402]
C67  0.01uF_25V  [C0402]
C68  0.1uF_25V  [C0402]
C70  0.1uF_25V  [C0402]
C71  0.1uF_25V  [C0402]
C73  22UF_16V  [C0805]
FB1  MPZ2012S601A  [FB0805]
FB2  MPZ2012S601A  [FB0805]
FB4  MPZ2012S601A  [FB0805]
FB5  MPZ2012S601A  [FB0805]
sheet PAGE05: IO PORT1
A31  M7685-05  [-]
J4  825433-2  [TE_825433-2]
LED2  LED_BLUE  [LED_0603]
R3  22 Ohm  [R0402]
R4  22 Ohm  [R0402]
R5  22 Ohm  [R0402]
R6  22 Ohm  [R0402]
R7  22 Ohm  [R0402]
R8  22 Ohm  [R0402]
R9  22 Ohm  [R0402]
R10  22 Ohm  [R0402]
R11  22 Ohm  [R0402]
R12  22 Ohm  [R0402]
R13  22 Ohm  [R0402]
R14  22 Ohm  [R0402]
R15  22 Ohm  [R0402]
R17  22 Ohm  [R0402]
R18  22 Ohm  [R0402]
R19  22 Ohm  [R0402]
R20  22 Ohm  [R0402]
R22  22 Ohm  [R0402]
R23  22 Ohm  [R0402]
R24  22 Ohm  [R0402]
R25  22 Ohm  [R0402]
R26  22 Ohm  [R0402]
R27  22 Ohm  [R0402]
R28  22 Ohm  [R0402]
R29  22 Ohm  [R0402]
R30  22 Ohm  [R0402]
R31  22 Ohm  [R0402]
R32  22 Ohm  [R0402]
R33  22 Ohm  [R0402]
R34  22 Ohm  [R0402]
R35  22 Ohm  [R0402]
R36  22 Ohm  [R0402]
R37  22 Ohm  [R0402]
R38  22 Ohm  [R0402]
R39  22 Ohm  [R0402]
R40  22 Ohm  [R0402]
R41  22 Ohm  [R0402]
R42  22 Ohm  [R0402]
R43  22 Ohm  [R0402]
R44  22 Ohm  [R0402]
R45  22 Ohm  [R0402]
R46  22 Ohm  [R0402]
R47  22 Ohm  [R0402]
R48  22 Ohm  [R0402]
R49  22 Ohm  [R0402]
R50  22 Ohm  [R0402]
R51  22 Ohm  [R0402]
R52  22 Ohm  [R0402]
R53  22 Ohm  [R0402]
R54  22 Ohm  [R0402]
R55  22 Ohm  [R0402]
R56  22 Ohm  [R0402]
R57  22 Ohm  [R0402]
R62  332 Ohm  [R0402]
R73  10K  [R0402]
R74  10K  [R0402]
U2  FX3_121_BUMP  [FX3_121_BUMP]  (sections A,B,C,D,E,F,G,H)
sheet PAGE06: I2C EEPROM & CONNECTORS
C43  0.1uF_25V  [C0402]
J6  ASP-181562-01  [SSW-120-03-G-D]
J7  ASP-181562-01  [SSW-120-03-G-D]
R71  2K  [R0402]
R72  2K  [R0402]
U6  M24M02-DRMN6TP  [SOIC127P600X175-8N_A]
sheet PAGE07: SRAM
A33  609 002 115 121  [-]
C13  0.1uF_25V  [C0402]
C14  0.1uF_25V  [C0402]
C15  0.1uF_25V  [C0402]
C16  0.1uF_25V  [C0402]
C17  0.1uF_25V  [C0402]
C18  0.1uF_25V  [C0402]
C19  0.1uF_25V  [C0402]
C20  0.1uF_25V  [C0402]
C21  0.1uF_25V  [C0402]
C22  0.1uF_25V  [C0402]
C23  0.1uF_25V  [C0402]
C24  0.1uF_25V  [C0402]
C25  0.1uF_25V  [C0402]
C26  0.1uF_25V  [C0402]
C27  0.1uF_25V  [C0402]
C28  0.1uF_25V  [C0402]
C29  0.1uF_25V  [C0402]
C30  0.1uF_25V  [C0402]
C31  0.1uF_25V  [C0402]
C32  0.1uF_25V  [C0402]
C33  0.1uF_25V  [C0402]
C34  0.1uF_25V  [C0402]
C35  2.2uF_25V  [C0603]
C36  2.2uF_25V  [C0603]
J5  961102-6404-AR  [TE_825433-2]
R58  2K  [R0402]
R66  10K  [R0402]
R67  10K  [R0402]
R68  0 Ohm  [R0402]
R69  0 Ohm  [R0402]
R70  10K  [R0402]
U5  CY7C1062DV33  [CY7C1062DV33-10BGXI]
sheet PAGE08:UART & JTAG
C37  0.01uF_25V  [C0402]
C38  1UF_16V  [CC0603]
C39  0.1uF_25V  [C0402]
C41  4.7uF / 25V  [CAPMP3216X180N]
C42  0.1uF_25V  [C0402]
C78  0.1uF_25V  [C0402]
C79  1UF_16V  [CC0603]
FB3  120E  [EMIFIL_BLM18P_0603]
J8  USB - MICRO B  [DX4R005J91R1500]
L1  BLM21PG221SN1D  [BLM21PG221SN1D]
R59  10K  [R0402]
R60  10K  [R0402]
R61  10K  [R0402]
R63  10K  [R0402]
U3  CY7C65215  [CY7C65215-32LTXI]
U4  USBLC6-2  [SOT95P280X145-6N]

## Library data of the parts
A30 A32 A33 = 4-881545-2: CONN SHUNT 2.54MM BLACK W/HANDLE; Alt.Manufacturer: Tyco Electronics; Manufacturer: Wurth Electronics Inc; PART_NUMBER: M50-2000005
C1 = CAPACITOR_NON-POL: CAP CER 10UF 10V 10% X7R 0805; Manufacturer: Taiyo Yuden; PART_NUMBER: LMK212B7106KG-TD
C2 = CAPACITOR_NON-POL: CAP CER 22UF 6.3V Y5V 80%  -20 % 1206; Manufacturer: Taiyo Yuden; PART_NUMBER: JMK316F226ZL-T
C3 C39 = CAP_NP: CAP CER 0.1UF 25V 10% X7R 0402; Dielectric: X7R; MANUFACTURER: TDK Corporation; PART_NUMBER: C1005X7R1E104K050BB; Tolerance: 10%; Type: Ceramic Capacitor; Voltage: 25V
C4 C69 = 10_uFd_Tantalum_16v_3216_2: CAP TANT 22UF 16V 10% 1210; DEVICE: 22uFd_tant_16v; Manufacturer: AVX Corporation; Mfr_Name: AVX Corporation; Mfr_Part_Number: TPSB226K016R0600; PART_NUMBER: TPSB226K016R0600
C5 C75 = 10_uFd_Tantalum_16v_3216_2: CAP 10UF 25V TANTALUM; DEVICE: 10uFd_tant_25v; Manufacturer: AVX Corporation; Mfr_Name: AVX Corporation; Mfr_Part_Number: TPSB106K025R1800; PART_NUMBER: TPSB106K025R1800
C74 = 1_1.0_uFd_0603_X5R_25V_10%: CAP CERAMIC 1.0UF 25V X5R 0603 10%; Manufacturer: Taiyo Yuden; PART_NUMBER: TMK107BJ105KA-T; VOLTAGE: 25V
C8 C9 C13-C34 C43 C44 C47 C48 C50 C51 C53-C55 C57 C61 C62 C64 C66 C68 C70 C71 C76 = Cap: CAP CER 0.1UF 25V 10% X7R 0402; FPLIST: 0201_rnd,0201; Manufacturer: TDK Corporation; PART_NUMBER: C1005X7R1E104K050BB; Tolerance: 10%
C77 C80 = CAP: CAP CER 1UF 16V 10% X7R 0603; Item Num: P03-15479R; Lead Free Status: Yes; Manufacturer: Taiyo Yuden; Num Pins: 2; PART_NUMBER: EMK107B7105KA-T; Part Class: CAPACITORS; RoHS Compliant: Yes
J1 = GSB3211311WEU_0: USB3.0 Connector; Manufacturer: FOXCONN
J2 = Header_1X2: HDR, CONN, HEADER, MALE, 2.54mm, 2POS, GOLD, TH; Alt.Manufacturer: Tyco Electronics; Alt.Part Number: 826926-2; Manufacturer: 3M; PART_NUMBER: GRPB021VWVN-RC; ROOM: DCDC-BOOST
J3 = Header_1X2: HDR, CONN, HEADER, MALE, 2.54mm, 2POS, GOLD, TH; Alt.Manufacturer: Tyco Electronics; Alt.Part Number: 826926-2; Manufacturer: 3M; ROOM: DCDC-BOOST
L1 L2 L4 = INDUCTOR: FERRITE CHIP 220 OHM 2000MA 0805; Manufacturer: Murata
L3 = INDUCTOR: INDUCTOR 2.2UH 1.20A 20% 1210; Lead Free: YES; Manufacturer: TDK Corporation
LED1 = LED: LED GREEN CLEAR 0603 SMD; CURRENT: 20mA; Manufacturer: Lite-On Inc; PART_NUMBER: LTST-C190KGKT; Voltage Rating: 2V
R2 = RES_0_OHM_1_10W_0402_SMD_0: RES 1.96K OHM 1/16W 1% 0402 SMD; Manufacturer: Yageo; Mfr_Part_Number: ERJ-3GEY0R00V; PART_NUMBER: RC0402FR-071K2L; Part Number: RC0402FR-071K96L
R16 = RESISTOR: RES 180 OHM 1/10W 5% 0402 SMD; Manufacturer: Panasonic Electronic Components; Mfr_Name: Panasonic Electronic Components; Mfr_Part_Number: ERJ-2RKF7320X; PART_NUMBER: ERJ-2GEJ181X; Tolerance: 1%
R21 R80 R82 = RES_0_OHM_1_10W_0402_SMD_3: RES 0.0 OHM 1/8W JUMP 0805 SMD; Manufacturer: Yageo; PART_NUMBER: RC0805JR-070RL
R78 = RESISTOR_5: RES 4.7K OHM 1/10W 5% 0402 SMD; CLASS: DISCRETE; DEVICE: 120_0603; Manufacturer: Yageo; Mfr_Name: Yageo; Mfr_Part_Number: RC0402FR-071K96L; PART_NUMBER: RC0402FR-071K96L; Part Number: ERJ-2GEJ472X
R79 = RESISTOR: RES 1.6K OHM 1/10W 1% 0402 SMD; Manufacturer: Panasonic Electronic Components; Mfr_Name: Panasonic Electronic Components; Mfr_Part_Number: ERJ-2RKF7320X; PART_NUMBER: ERJ-2RKF7320X; Part Number: ERJ-2RKF1601X; Tolerance: 1%
R81 = RESISTOR: RES 120 OHM 1/10W 5% 0402 SMD; Manufacturer: Panasonic Electronic Components; Mfr_Name: Panasonic Electronic Components; Mfr_Part_Number: ERJ-2RKF7320X; No_Mount: DNL; PART_NUMBER: ERJ-2GEJ121X; Tolerance: 1%
R62 R83 = RESISTOR: RES 332 OHM 1/10W 1% 0402 SMD; Manufacturer: Panasonic Electronic Components; PART_NUMBER: ERJ-2RKF3320X
TP1 TP2 = TP_LOOP_RED: TEST POINT PC MINI .040"D BLACK; PART_NUMBER: 5001
TP4-TP6 = T_POINT_A
U1 = LM1117MPX-3_1.3_SOT223: Manufacturer: ON Semiconductor; Section: Power_supply
U7 = LM1117MPX-3_1.3_SOT223: Manufacturer: OnSemi; Mfr_Name: OnSemi; Section: Power_supply
U8 = AZ1065-06Q_0: TVS ARRAY ESD 4CH .45PF 8KV UDFN; Manufacturer: Littlefuse; PART_NUMBER: SP3010-04UTG
U9 = USBLC6-2_0: IC ESD PROTECTION LO CAP SOT23-6; DISTRIBUTER'S P/N: 497-5235-1-ND; LEAD FREE: Y; MANUFACTURER: ST Micro.; MANUFACTURER P/N: USBLC6-2SC6; Type: ESD Protection IC; UNIT COST: $0.36; Voltage: 5V
U10 = SC189CSKTRT: IC REG BUCK SYNC 1.2V SOT23-5; Manufacturer: Semtech
U11 = NCP361SNT1G_0: IC USB POS OVP/OC_TSOP5; Manufacturer: ON Semiconductor
C10 C40 C72 = CAPACITOR_NON-POL: CAP CER 0.1UF 25V 10% X7R 0402; Manufacturer: TDK Corporation; PART_NUMBER: C1005X7R1E104K050BB; Tolerance: 10%
C11 C12 = 12_pFd_0805_1: CAP CER 13PF 50V 2% NP0 0402; Manufacturer: Johanson Technology Inc; PART_NUMBER: 500R07S130GV4T
R1 R64 = R: RES 100K OHM 1/10W 1% 0402 SMD; Manufacturer: PANASONIC; PART_NUMBER: ERJ-2RKF1003X
R75 = R: RES 200 OHM 1/10W 1% 0402 SMD; Manufacturer: PANASONIC; PART_NUMBER: ERJ-2RKF2000X
R61 R73 R74 R76 = R: RES 10.0K OHM 1/16W 1% 0402 SMD; Manufacturer: Vishay; Manufaturer: Vishay; PART_NUMBER: CRCW040210K0FKED
R77 = R: RES 6.04K OHM 1/10W 1% 0402 SMD; Manufacturer: PANASONIC; Manufaturer: Vishay; PART_NUMBER: ERJ-2RKF6041X
SW1 = EVQ-PE105K: SWITCH TACTILE SPST-NO 0.05A 12V; FPLIST: PBSPST,PUSHBUTTON_EVQ; Item Num: P11-24000R; Lead Free Status: No; Manufacturer: Panasonic Electronic Components; Mfr Code: PAN; Num Pins: 2; Part Class: Switches; Part Number: 434 123 050 816; Price: 0.72; RoHS Compliant: Yes
SW2 = EVQ-PE105K: SWITCH TACTILE SPST-NO 0.05A 12V; FPLIST: PBSPST,PUSHBUTTON_EVQ; Item Num: P11-24000R; Lead Free Status: No; Manufacturer: Panasonic Electronic Components; Mfr Code: PAN; Num Pins: 2; Part Class: Switches; Price: 0.72; RoHS Compliant: Yes
Y1 = CRYSTAL_1: SMD CRYSTAL 19.2 MHZ; Manufacturer: NDK America; PART_NUMBER: NX2520SA-19.200000MHZ-NBG1
C6 C45 C73 = Cap: CAP CER 22UF 16V 10% X5R 0805; FPLIST: 0603_rnd,0603; Manufacturer: TDK; PART_NUMBER: C2012X5R1C226K; TEMPCO: X5R; Tolerance: 10%; VOLTAGE: 16V
C7 C35 C36 = Cap: CAP CER 2.2UF 10V 20% X5R 0603; FPLIST: 0603_rnd,0603; Manufacturer: Murata; PART_NUMBER: GRM188R61A225ME34D; Tolerance: 10%
C46 C49 C52 C56 C58-C60 C63 C65 C67 = Cap: CAP CERM .01UF 10% 25V X7R 0402; FPLIST: 0201_rnd,0201; Manufacturer: AVX; PART_NUMBER: 04023C103KAT2A; Tolerance: 10%
FB1 FB2 FB4 FB5 = INDUCTOR_v3: FERRITE CHIP BEAD 600 OHM SMD 2.0A; Manufacturer: TDK
A31 = 4-881545-2: CONN SHUNT 2.54MM BLACK W/HANDLE; Alt.Manufacturer: Tyco Electronics; Manufacturer: Harwin Inc
J4 = Header_1X2: CONN HEADER VERT SGL 2POS GOLD; Alt.Manufacturer: Tyco Electronics; Alt.Part Number: 826926-2; Manufacturer: TE Connectivity; ROOM: DCDC-BOOST
LED2 = LED: LED BLUE 0603 SMD; CURRENT: 20mA; Manufacturer: Lite-On Inc; PART_NUMBER: LTST-C190KGKT; Part Number: LTST-C193TBKT-5A; Voltage Rating: 2V
R3-R15 R17-R20 R22-R57 = R: RES 22.0 OHM 1/10W 1% 0402 SMD; Manufacturer: Panasonic - ECG; Manufaturer: Panasonic - ECG; PART_NUMBER: ERJ-2RKF22R0X
U2 = FX3_121_BUMP_10: FX3; Manufacturer: Cypress
J6 J7 = CPU_CONNECTOR_0: CONN HEADER FMAL 40PS.1" DL GOLD; Manufacturer: Samtec
R71 R72 = R: RES 2.00K OHM 1/16W 1% 0402 SMD; Manufacturer: Vishay; Manufaturer: Vishay; PART_NUMBER: CRCW04022K00FKED
U6 = M24M02-DR: IC EEPROM 2MBIT 1MHZ 8SOIC; Manufacturer: STMicroelectronics
J5 = Header_1X2: CONN HEHDR, CONN, HEADER, MALE, 2.54mm, 2POS, GOLD, TH / ADER .050 2POS PCB GOLD; Alt.Manufacturer: Tyco Electronics; Alt.Part Number: 826926-2; Manufacturer: 3M; ROOM: DCDC-BOOST
R58 = RESISTOR: RES 2.00K OHM 1/16W 1% 0402 SMD; Manufacturer: Vishay; PART_NUMBER: CRCW04022K00FKED
R59 R66 = RESISTOR: RES 10.0K OHM 1/16W 1% 0402 SMD; Manufacturer: Vishay; PART_NUMBER: CRCW040210K0FKED
R67 R70 = RESISTOR: RES 10.0K OHM 1/16W 1% 0402 SMD; Manufacturer: Vishay; No_Mount: DNL; PART_NUMBER: CRCW040210K0FKED
R68 R69 = R: RES 0.0 OHM 1/16W JUMP 0402 SMD; Manufacturer: Yageo; Manufaturer: Panasonic - ECG; PART_NUMBER: RC0402JR-070RL
U5 = CY7C1062DV33
C37 = Cap: CAP CERM .01UF 10% 25V X7R 0402; FPLIST: 0201_rnd,0201; Manufacturer: AVX; No_Mount: DNL; PART_NUMBER: 04023C103KAT2A; Tolerance: 10%
C38 C79 = CAPACITOR_NON-POL: CAP CER 1UF 16V 10% X7R 0603; Manufacturer: Taiyo Yuden; PART_NUMBER: EMK107B7105KA-T
C41 = CAP: CAP TANT 4.7UF 25V 20% 1206; Manufacturer: Kemet; PART_NUMBER: T491A475M025AT
C42 C78 = Cap: CAP CER 0.1UF 25V 10% X7R 0402; FPLIST: 0201_rnd,0201; Manufacturer: Murata; PART_NUMBER: GRM155F51E104ZA01D; Tolerance: 10%
FB3 = FERRITE_120_OHM_2000MA_0: Manufacturer: Murata; PART_NUMBER: BLM18PG121SN1D
J8 = DX4R005J91R1500: CONN RCPT 5POS R/A MICRO USB; Manufacturer: JAE Electronics
R60 = RESISTOR: RES 10.0K OHM 1/16W 1% 0402 SMD; Manufacturer: Vishay; No_Mount: DNL; PART_NUMBER: CRCW040210K0FKED; Part Number: CRCW040210K0FKED
R63 = R: RES 10.0K OHM 1/16W 1% 0402 SMD; Manufacturer: Vishay; Manufaturer: Vishay; No_Mount: DNL; PART_NUMBER: CRCW040210K0FKED
U3 = CY7C65215_4
U4 = USBLC6-2_0: IC ESD PROTECTION LO CAP SOT23-6; DISTRIBUTER'S P/N: 497-5235-1-ND; LEAD FREE: Y; MANUFACTURER: ST Micro.; MANUFACTURER P/N: USBLC6-2SC6; PART_NUMBER: USBLC6-2SC6; Type: ESD Protection IC; UNIT COST: $0.36; Voltage: 5V

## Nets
AVDD: C7.1 C71.1 FB4.1 U2.A7(AVDD)
GND: C1.2 C2.2 C3.2 C4.2 C5.2 C6.2 C7.2 C10.2 C11.2 C12.1 C13.2 C14.2 C15.2 C16.2 C17.2 C18.2 C19.2 C20.2 C21.2 C22.2 C23.2 C24.2 C25.2 C26.2 C27.2 C28.2 C29.2 C30.2 C31.2 C32.2 C33.2 C34.2 C35.2 C36.2 C37.2 C38.1 C39.2 C40.2 C41.2 C42.2 C43.2 C44.2 C45.2 C46.2 C47.2 C48.2 C49.2 C50.2 C51.2 C52.2 C53.2 C54.2 C55.2 C56.2 C57.2 C58.2 C59.2 C60.2 C61.2 C62.2 C63.2 C64.2 C65.2 C66.2 C67.2 C68.2 C69.2 C70.2 C71.2 C72.2 C73.2 C74.2 C75.2 C76.2 C77.2 C78.2 C79.1 C80.2 J1.4(GND1) J1.7(GND-DRAIN) J6.5 J6.6 J6.33 J6.37 J7.13 J7.15 J7.17 J7.25 J7.29 J7.39 J7.40 J8.4(GND) L1.2 L4.2 LED1.2(CATHODE) R2.1 R16.1 R58.1 R60.2 R63.1 R75.2 R76.1 R77.2 R81.1 SW1.A1 SW2.B1 TP1.1 TP2.1 U1.1(ADJ) U2.A1(U3VSSQ) U2.A8(VSS12) U2.B7(AVSS) U2.B8(VSS14) U2.B9(VSS13) U2.D8(VSS5) U2.E2(VSS3) U2.G1(VSS1) U2.G11(VSS6) U2.K3(VSS10) U2.K4(VSS8) U2.L1(VSS2) U2.L2(VSS11) U2.L3(VSS9) U2.L6(VSS4) U2.L11(VSS7) U3.4(VSSD) U3.17(VSSD2) U3.20(VSSD3) U3.24(VSSA) U3.33(E-PAD) U4.2(G) U5.D3(VSS1) U5.D4(VSS2) U5.D5(VSS3) U5.E2(VSS4) U5.E4(VSS5) U5.E6(VSS6) U5.F3(VSS7) U5.F4(VSS8) U5.F5(VSS9) U5.G2(VSS10) U5.G4(VSS11) U5.G6(VSS12) U5.H3(VSS13) U5.H4(VSS14) U5.H5(VSS15) U5.J2(VSS16) U5.J4(VSS17) U5.J6(VSS18) U5.K3(VSS19) U5.K4(VSS20) U5.K5(VSS21) U5.L2(VSS22) U5.L4(VSS23) U5.L6(VSS24) U5.M3(VSS25) U5.M4(VSS26) U5.M5(VSS27) U5.N2(VSS28) U5.N4(VSS29) U5.N6(VSS30) U5.P3(VSS31) U5.P4(VSS32) U5.P5(VSS33) U6.4(VSS) U8.3 U8.8 U9.2(G) U10.2(GND) U11.2(GND) U11.3(EN_L) Y1.2 Y1.4
V1P2: C44.1 C45.1 C47.1 C49.1 C50.1 C54.1 C57.1 C58.1 C62.1 C63.1 C67.1 FB1.2 FB4.2 FB5.2 J6.2 J7.2 R82.2 TP5.1(TP) U2.B10(VDD8) U2.C3(VDD2) U2.E9(VDD4) U2.F11(VDD5) U2.H1(VDD1) U2.J11(VDD7) U2.L5(VDD6) U2.L7(VDD3)
V3P3: C13.1 C14.1 C15.1 C16.1 C17.1 C18.1 C19.1 C20.1 C21.1 C22.1 C23.1 C24.1 C25.1 C26.1 C27.1 C28.1 C29.1 C30.1 C31.1 C32.1 C33.1 C34.1 C35.1 C36.1 C41.1 C42.1 C43.1 C60.1 C61.1 C65.1 C66.1 FB2.1 J6.1 J7.1 LED2.1(ANODE) R1.2 R59.1 R61.1 R66.2 R67.2 R70.2 R71.2 R72.2 R80.2 TP6.1(TP) U2.B1(VIO4) U2.C11(VIO5) U3.1(VDDD) U3.23(VDDD2) U5.D2(VDD1) U5.D6(VDD2) U5.E3(VDD3) U5.E5(VDD4) U5.F2(VDD5) U5.F6(VDD6) U5.G3(VDD7) U5.G5(VDD8) U5.H2(VDD9) U5.H6(VDD10) U5.J3(VDD11) U5.J5(VDD12) U5.K2(VDD13) U5.K6(VDD14) U5.L3(VDD15) U5.L5(VDD16) U5.M2(VDD17) U5.M6(VDD18) U5.N3(VDD19) U5.N5(VDD20) U5.P2(VDD21) U5.P6(VDD22) U6.8(VCC)
VBUS_IN: C3.1 C80.1 L2.2 U9.5(V) U11.1(IN)
CTL0: J5.1 J6.31 R53.2
CTL1: J6.29 R40.2 R68.1
CTL2: J6.27 R54.2 R69.1
CTL3: J6.25 R39.2
CTL4_SW: J6.23 R33.2
CTL5: J6.21 R57.2 U5.A2(A1)
CTL6: J6.19 R41.2 U5.A3(A2)
CTL7: J6.17 R50.2 U5.A4(A3)
CTL8: J6.15 R22.2 U5.A5(A4)
CTL9: J6.13 R42.2 U5.A6(A5)
CTL10: J6.11 R43.2 U5.B2(A6)
CTL11: J6.9 R56.2 U5.B3(A7)
CTL12: J6.7 R44.2 U5.B5(A8)
D+: J8.3(DP) U4.1(IO1A)
D-: J8.2(DM) U4.3(IO2A)
DQ0: J6.38 R46.2 U5.A7(IO0)
DQ1: J6.36 R45.2 U5.B7(IO1)
DQ2: J6.34 R27.2 U5.C7(IO2)
DQ3: J6.32 R47.2 U5.D7(IO3)
DQ4: J6.30 R32.2 U5.E7(IO4)
DQ5: J6.28 R30.2 U5.F7(IO5)
DQ6: J6.26 R48.2 U5.G7(IO6)
DQ7: J6.24 R34.2 U5.H7(IO7)
DQ8: J6.22 R49.2 U5.K7(IO8)
DQ9: J6.20 R37.2 U5.L7(IO9)
DQ10: J6.18 R35.2 U5.M7(IO10)
DQ11: J6.16 R51.2 U5.N7(IO11)
DQ12: J6.14 R36.2 U5.P7(IO12)
DQ13: J6.12 R52.2 U5.R7(IO13)
DQ14: J6.10 R38.2 U5.T7(IO14)
DQ15: J6.8 R19.2 U5.U7(IO15)
DQ16: J7.38 R29.2 U5.A1(IO16)
DQ17: J7.36 R31.2 U5.B1(IO17)
DQ18: J7.34 R26.2 U5.C1(IO18)
DQ19: J7.32 R25.2 U5.D1(IO19)
DQ20: J7.30 R28.2 U5.E1(IO20)
DQ21: J7.28 R24.2 U5.F1(IO21)
DQ22: J7.26 R20.2 U5.G1(IO22)
DQ23: J7.24 R23.2 U5.H1(IO23)
DQ24: J7.22 R13.2 U5.K1(IO24)
DQ25: J7.20 R18.2 U5.L1(IO25)
DQ26: J7.18 R17.2 U5.M1(IO26)
DQ27: J7.16 R15.2 U5.N1(IO27)
DQ28: J7.12 R8.2 U5.P1(IO28)
DQ29: J7.10 R14.2 U5.R1(IO29)
DQ30: J7.8 R3.2 U5.T1(IO30)
DQ31: J7.6 R7.2 U5.U1(IO31)
FSLC0: R76.2 U2.B2(FSLC0) U2.B4(FSLC1) U2.E6(FSLC2)
GPIO45: C40.1 J7.14 R64.1 SW2.A1 U2.F2(GPIO45)
GPIO57_I2S-MCLK_VIO3_SW: J7.35 R6.2
I2C_SCL_FX3: J6.40 R72.1 U2.D9(I2C-GPIO58_SCL) U3.28(SCB0_2/GPIO_3/RTS#_0) U6.6(SCL)
I2C_SDA_FX3: J6.39 R71.1 U2.D10(I2C-GPIO59_SDA) U3.29(SCB0_3/GPIO_4/CTS#_0) U6.5(SDA)
I2S_CLK: J7.37 R12.2
I2S_SD: J7.33 R10.2
I2S_WS: J7.31 R11.2
INT_N_CTL15: J7.3 U2.L8(INT_N_CTL15)
PCLK: J6.35 R55.2
PMODE_0: J4.1 J7.11 U2.G4(PMODE0)
PMODE_1: J7.9 R73.2 U2.H4(PMODE1)
PMODE_2: J7.7 U2.L4(PMODE2)
RESET_IN: C72.1 R1.1 SW1.B1 U2.C5(RESET_N)
SPI-MISO_UART-TX: J7.21 R9.2 U3.2(SCB0_0/GPIO_8/RXD_0)
SPI-MOSI_UART-RX: J7.19 R4.2 U3.30(SCB0_4/GPIO_5/TXD_0)
SPI-SCK_UART-RTS: J7.27 R5.2
SPI-SSN_UART-CTS: J7.23 R62.1 U2.C1(UART-CTS_SPI-SSN)
SS_DM: U2.A10(DM) U9.6(IO1B)
SS_DP: U2.A9(DP) U9.4(IO2B)
SS_RX_M: J1.9(STDB_SSRX+) U2.A3(SSRXM) U8.5 U8.6
SS_RX_P: J1.8(STDB_SSRX-) U2.A4(SSRXP) U8.4 U8.7
SS_TX_M: C8.2 J1.5(STDB_SSTX-) U8.1 U8.10
SS_TX_P: C9.2 J1.6(STDB_SSTX+) U8.2 U8.9
SSDM: J1.2(D-) U9.1(IO1A)
SSDP: J1.3(D+) U9.3(IO2A)
U3RX_VDDQ: C68.1 C73.1 FB5.1 U2.A2(U3RXVDDQ)
U3TX_VDDQ: C6.1 C70.1 FB1.1 U2.B5(U3TXVDDQ)
USB3_VBUS: C1.1 C5.1 C10.1 C75.1 C77.1 J6.3 J6.4 U1.3(VIN) U2.E11(VBUS) U7.3(VIN) U10.1(IN1) U10.3(EN) U11.5(OUT)
V_BUS: C39.1 C78.1 C79.2 FB3.2 U3.19(VBUS) U4.5(V)
VIO: C46.1 C48.1 C51.1 C52.1 C53.1 C55.1 C56.1 J7.4 R21.2 R64.2 R73.1 R74.1 TP4.1(TP) U2.E3(VIO3) U2.F1(VIO2) U2.H11(VIO1_2) U2.L9(VIO1_1)
XTALIN: C11.1 U2.C6(XTALIN) Y1.1
XTALOUT: C12.2 U2.C7(XTALOUT) Y1.3
N02063: C76.1 J1.10(SHIELD1) J1.11(SHIELD2) L4.1
N16673785: C59.1 C64.1 FB2.2 U2.B6(CVDDQ)
N16678744: R22.1 U2.G5(CTL8)
N16678748: R50.1 U2.H8(CTL7)
N16678768: R43.1 U2.K5(CTL10)
N16678772: R42.1 U2.H6(CTL9)
N16678828: R56.1 U2.J5(CTL11)
N16678842: R44.1 U2.H5(CTL12)
N16678980: R46.1 U2.F10(DQ0)
N16679050: R45.1 U2.F9(DQ1)
N16679094: R27.1 U2.F7(DQ2)
N16679146: R47.1 U2.G10(DQ3)
N16679206: R48.1 U2.H10(DQ6)
N16679210: R30.1 U2.F8(DQ5)
N16679214: R32.1 U2.G9(DQ4)
N16679250: R34.1 U2.H9(DQ7)
N16679742: R35.1 U2.K11(DQ10)
N16679746: R37.1 U2.J9(DQ9)
N16679750: R49.1 U2.J10(DQ8)
N16679786: R51.1 U2.L10(DQ11)
N16679852: R52.1 U2.K9(DQ13)
N16679856: R36.1 U2.K10(DQ12)
N16679876: R19.1 U2.G8(DQ15)
N16679880: R38.1 U2.J8(DQ14)
N16679932: R40.1 U2.K7(CTL1)
N16679936: R53.1 U2.K8(CTL0)
N16679940: R55.1 U2.J6(PCLK)
N16679976: R54.1 U2.J7(CTL2)
N16680012: R33.1 U2.G7(CTL4)
N16680016: R39.1 U2.H7(CTL3)
N16680036: R41.1 U2.K6(CTL6)
N16680040: R57.1 U2.G6(CTL5)
N16683802: R31.1 U2.J4(DQ17)
N16683812: R29.1 U2.K2(DQ16)
N16683838: R26.1 U2.K1(DQ18)
N16683870: R25.1 U2.J2(DQ19)
N16683912: R28.1 U2.J3(DQ20)
N16683932: R20.1 U2.H2(DQ22)
N16683942: R24.1 U2.J1(DQ21)
N16683968: R23.1 U2.H3(DQ23)
N16684000: R13.1 U2.F4(DQ24)
N16684042: R18.1 U2.G2(DQ25)
N16684068: R17.1 U2.G3(DQ26)
N16684104: R15.1 U2.F3(DQ27)
N16684224: R8.1 U2.F5(DQ28)
N16684244: R3.1 U2.E5(DQ30)
N16684254: R14.1 U2.E1(DQ29)
N16684280: R7.1 U2.E4(DQ31)
N16684392: R10.1 U2.D2(I2S-SD)
N16684396: R12.1 U2.D1(I2S-CLK)
N16684460: R11.1 U2.D3(I2S-WS)
N16684510: R6.1 U2.C4(I2S-MCLK)
N16684546: R9.1 U2.C2(UART-TX_SPI-MISO)
N16684554: R5.1 U2.D4(UART-RTS_SPI-SCK)
N16684574: R4.1 U2.D5(UART-RX_SPI-MOSI)
N16689306: C9.1 U2.A5(SSTXP)
N16689332: C8.1 U2.A6(SSTXM)
N16689459: R77.1 U2.C8(R_USB2)
N16694632: C38.2 U3.16(VCCD)
N16695427: J8.5(SHIELD1) J8.6(SHIELD2) J8.7(SHIELD3) J8.8(SHIELD4) J8.9(SHIELD5) J8.10(SHIELD6) L1.1
N16695451: FB3.1 J8.1(VBUS)
N16695553: U3.14(USBDP) U4.6(IO1B)
N16695561: U3.15(USBDM) U4.4(IO2B)
N16697030: R59.2 R63.2 U3.12(WAKEUP)
N16697037: C37.1 R61.2 U3.18(XRESN)
N16734416: R58.2 U5.B6(A9) U5.C2(BCN) U5.C3(CE2N) U5.C5(CE3N) U5.C6(BAN) U5.R2(A10) U5.R3(BDN) U5.R5(BBN) U5.R6(A11) U5.T2(A12) U5.T3(A13) U5.T5(A14) U5.T6(A15) U5.U2(A16) U5.U3(A17) U5.U5(A18) U5.U6(A19)
N16735835: J5.2 R66.1 U5.B4(CE1N)
N16736019: R67.1 R68.2 U5.T4(WEN)
N16736247: R69.2 R70.1 U5.U4(OEN)
N16824660: U2.F6(TCK) U3.8(SCB1_3/GPIO_13/CTS#_1)
N16824680: U2.E7(TDI) U3.6(SCB1_1/GPIO_11/TXD_1)
N16824700: U2.C10(TDO) U3.5(SCB1_0/GPIO_10/RXD_1)
N16824720: U2.E8(TMS) U3.7(SCB1_2/GPIO_12/RTS#_1)
N16824740: U2.B11(TRST_N) U3.9(SCB1_4/GPIO_14/DSR#_1)
N16838394: C4.1 R80.1 R83.2 U1.2(VOUT) U1.4(TAB)
N16841024: L3.1 U10.5(LX)
N16841026: C2.1 L3.2 R81.2 R82.1 U10.4(VOUT)
N16887907: J4.2 R74.2
N16887965: J3.2 L2.1
N16887968: J1.1(VBUS) J3.1
N16904489: C69.1 R16.2 R21.1 R78.2 R79.2 U7.2(VOUT) U7.4(TAB)
N16904549: C74.1 J2.2 R2.2 R78.1 U7.1(ADJ)
N16904665: J2.1 R79.1
N17011056: LED2.2(CATHODE) R62.2
N17082147: R75.1 U2.B3(R_USB3)
N17153947: R60.1 U3.27(SCB0_1/GPO_2/DSR#_0)
N17201866: LED1.1(ANODE) R83.1

Not connected (* = marked no-connect by the designer): J7 5*; U2 A11(NC)* C9(OTG_ID)* D6(CLKIN_32)* D7(CLKIN)* D11(I2C-GPIO60_CHARGER-DETECT)* E10(VBAT)*; U3 3(SCB0_5/GPIO_9/DTR#_0)* 10(SCB1_5/GPIO_15/DTR#_1)* 11(SUSPEND)* 13(GPIO_16/TRISTATE)* 21(GPIO_17/TRISTATE)* 22(GPIO_18/TRISTATE)* 25(GPIO_0/TXLED#)* 26(GPIO_1/RXLED#)* 31(GPIO_6/POWER#)* 32(GPIO/TRISTATE)*; U5 C4(NC1)* J1(NC2)* J7(NC3)* R4(NC4)*; U6 1(DU1)* 2(DU2)* 3(E2)* 7(~{WC})*; U11 4(FLAG)*

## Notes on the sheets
sheet 1
- FX3 POWER & DECOUPLING
- PCA: 121-60162-01
  PCB: 600-60198-01
  FAB DRW: 610-60190-01
  ASSY DRW: 620-60198-01
- CYUSB3KIT-003
sheet 2
- IO PORT 1
- IO PORT 2
- IO PORT 3
- PCA: 121-60162-01
  PCB: 600-60198-01
  FAB DRW: 610-60190-01
  ASSY DRW: 620-60198-01
- CYUSB3KIT-003
sheet 3
- SRAM  INTERFACE
- PCA: 121-60162-01
  PCB: 600-60198-01
  FAB DRW: 610-60190-01
  ASSY DRW: 620-60198-01
- CYUSB3KIT-003
sheet 4
- RESET_CIRCUIT
- CLOCK SIGNALS
- FX3 USB3.0
- TACTILE SWITCH
- PCA: 121-60162-01
  PCB: 600-60198-01
  FAB DRW: 610-60190-01
  ASSY DRW: 620-60198-01
- CYUSB3KIT-003
sheet 5
- USB TO SERIAL / JTAG CONVERTER
- USB MICRO-B
- PCA: 121-60162-01
  PCB: 600-60198-01
  FAB DRW: 610-60190-01
  ASSY DRW: 620-60198-01
- CYUSB3KIT-003
sheet 6
- PAGE 01
- INDEX PAGE
- PAGE 02
- POWER SUPPLY
- PAGE 03
- FX3 CLOCK & RESET
- PAGE 04
- FX3 POWER
- PAGE 05
- FX3 IO PORTS
- PAGE 06
- EEPROM & CONNECTORS
- PAGE 07
- SRAM
- PAGE 08
- UART & JTAG
- PCA: 121-60162-01
  PCB: 600-60198-01
  FAB DRW: 610-60190-01
  ASSY DRW: 620-60198-01
- CYUSB3KIT-003
sheet 7
- ESD
  DEVICE
- USB POSITIVE
  OVERVOLTAGE
- PROTECTION
  CONTROLLER
- USB3.0 TYPE
  B
- VIO = 1.8V, When J2 is Open.
- 3.3V  @ 1.5A
  REGULATOR
- VIO = 3.3V, When J2 is Shorted.
- LDO
- LDO
- 3.3V / 1.8V @ 1.5A
  REGULATOR FOR VIO
- 1.2V @ 1.5A
  REGULATOR
- PCA: 121-60162-01
  PCB: 600-60198-01
  FAB DRW: 610-60190-01
  ASSY DRW: 620-60198-01
- CYUSB3KIT-003
sheet 8
- I2C EEPROM
- RECTANGULAR HEADERS FOR EXPANSION
- PCA: 121-60162-01
  PCB: 600-60198-01
  FAB DRW: 610-60190-01
  ASSY DRW: 620-60198-01
- CYUSB3KIT-003
